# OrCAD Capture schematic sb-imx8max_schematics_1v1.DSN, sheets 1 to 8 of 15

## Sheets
1 14. HDMI_RX: size A; title: 14. HDMI_RX; rev: 1.1
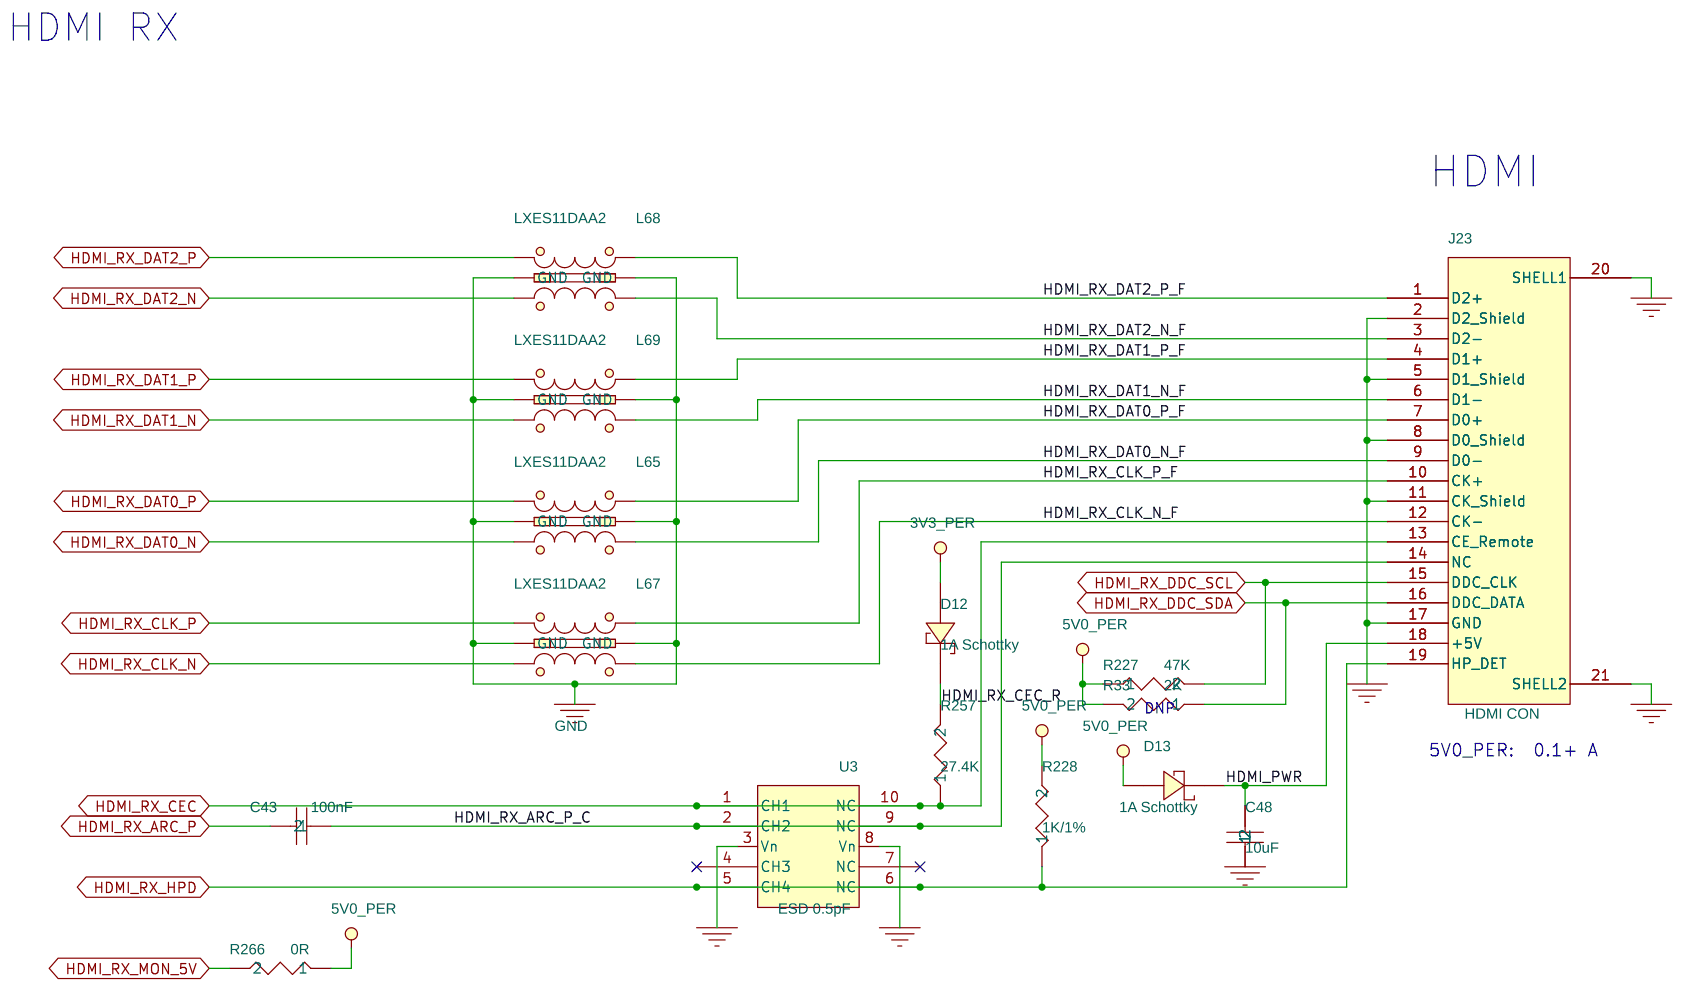
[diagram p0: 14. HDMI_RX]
2 13. AUDIO: size B; title: 13. AUDIO
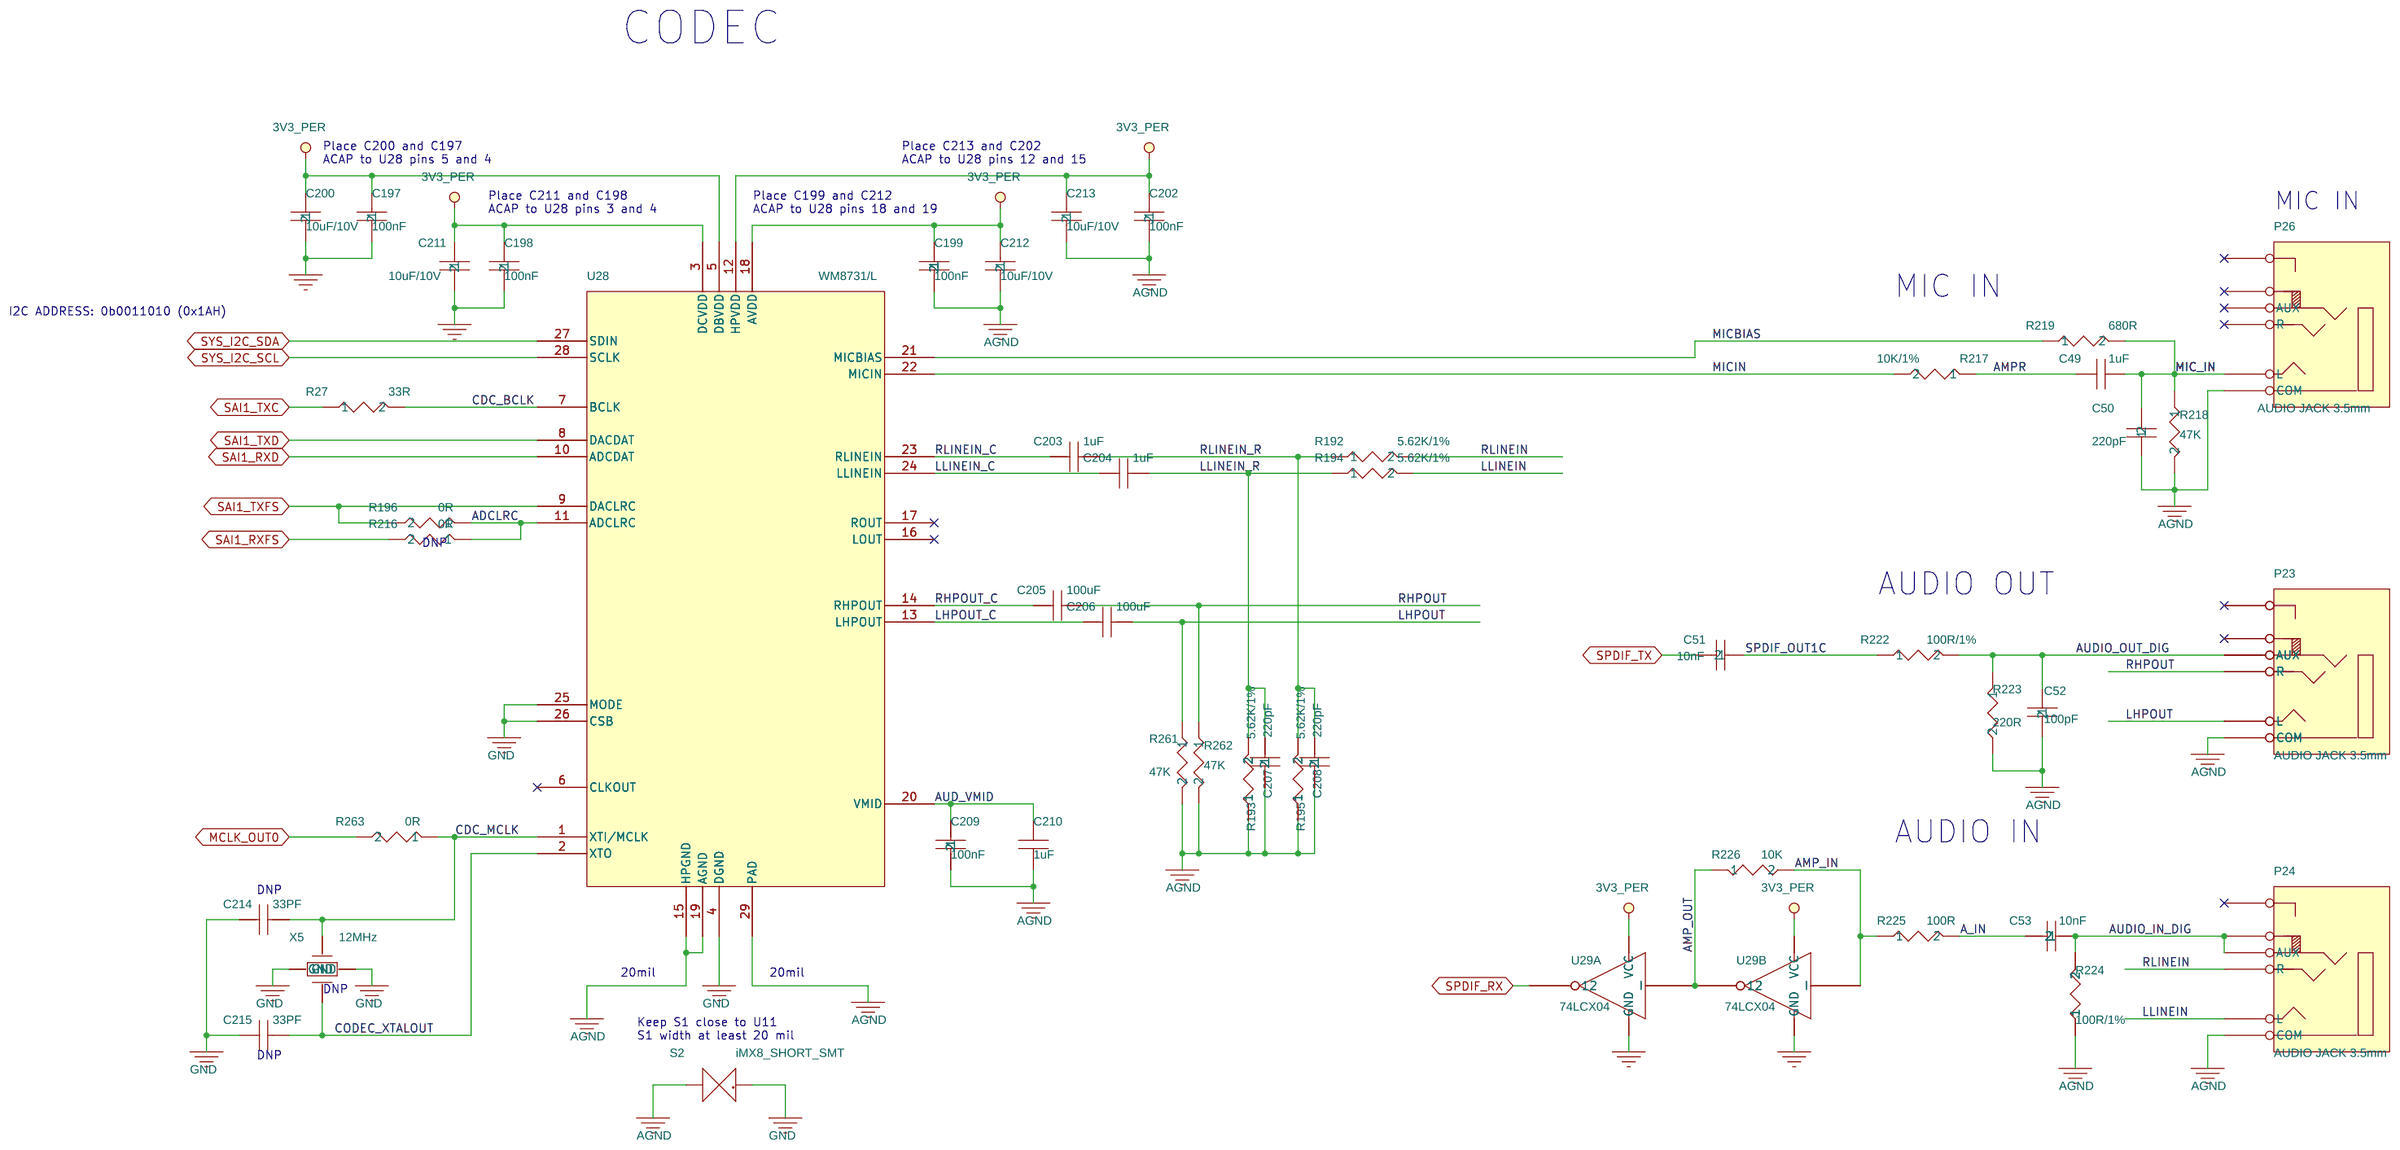
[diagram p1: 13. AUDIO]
3 12. LVDS 2CH DISPLAY: size B; title: 12. LVDS 2CH DISPLAY
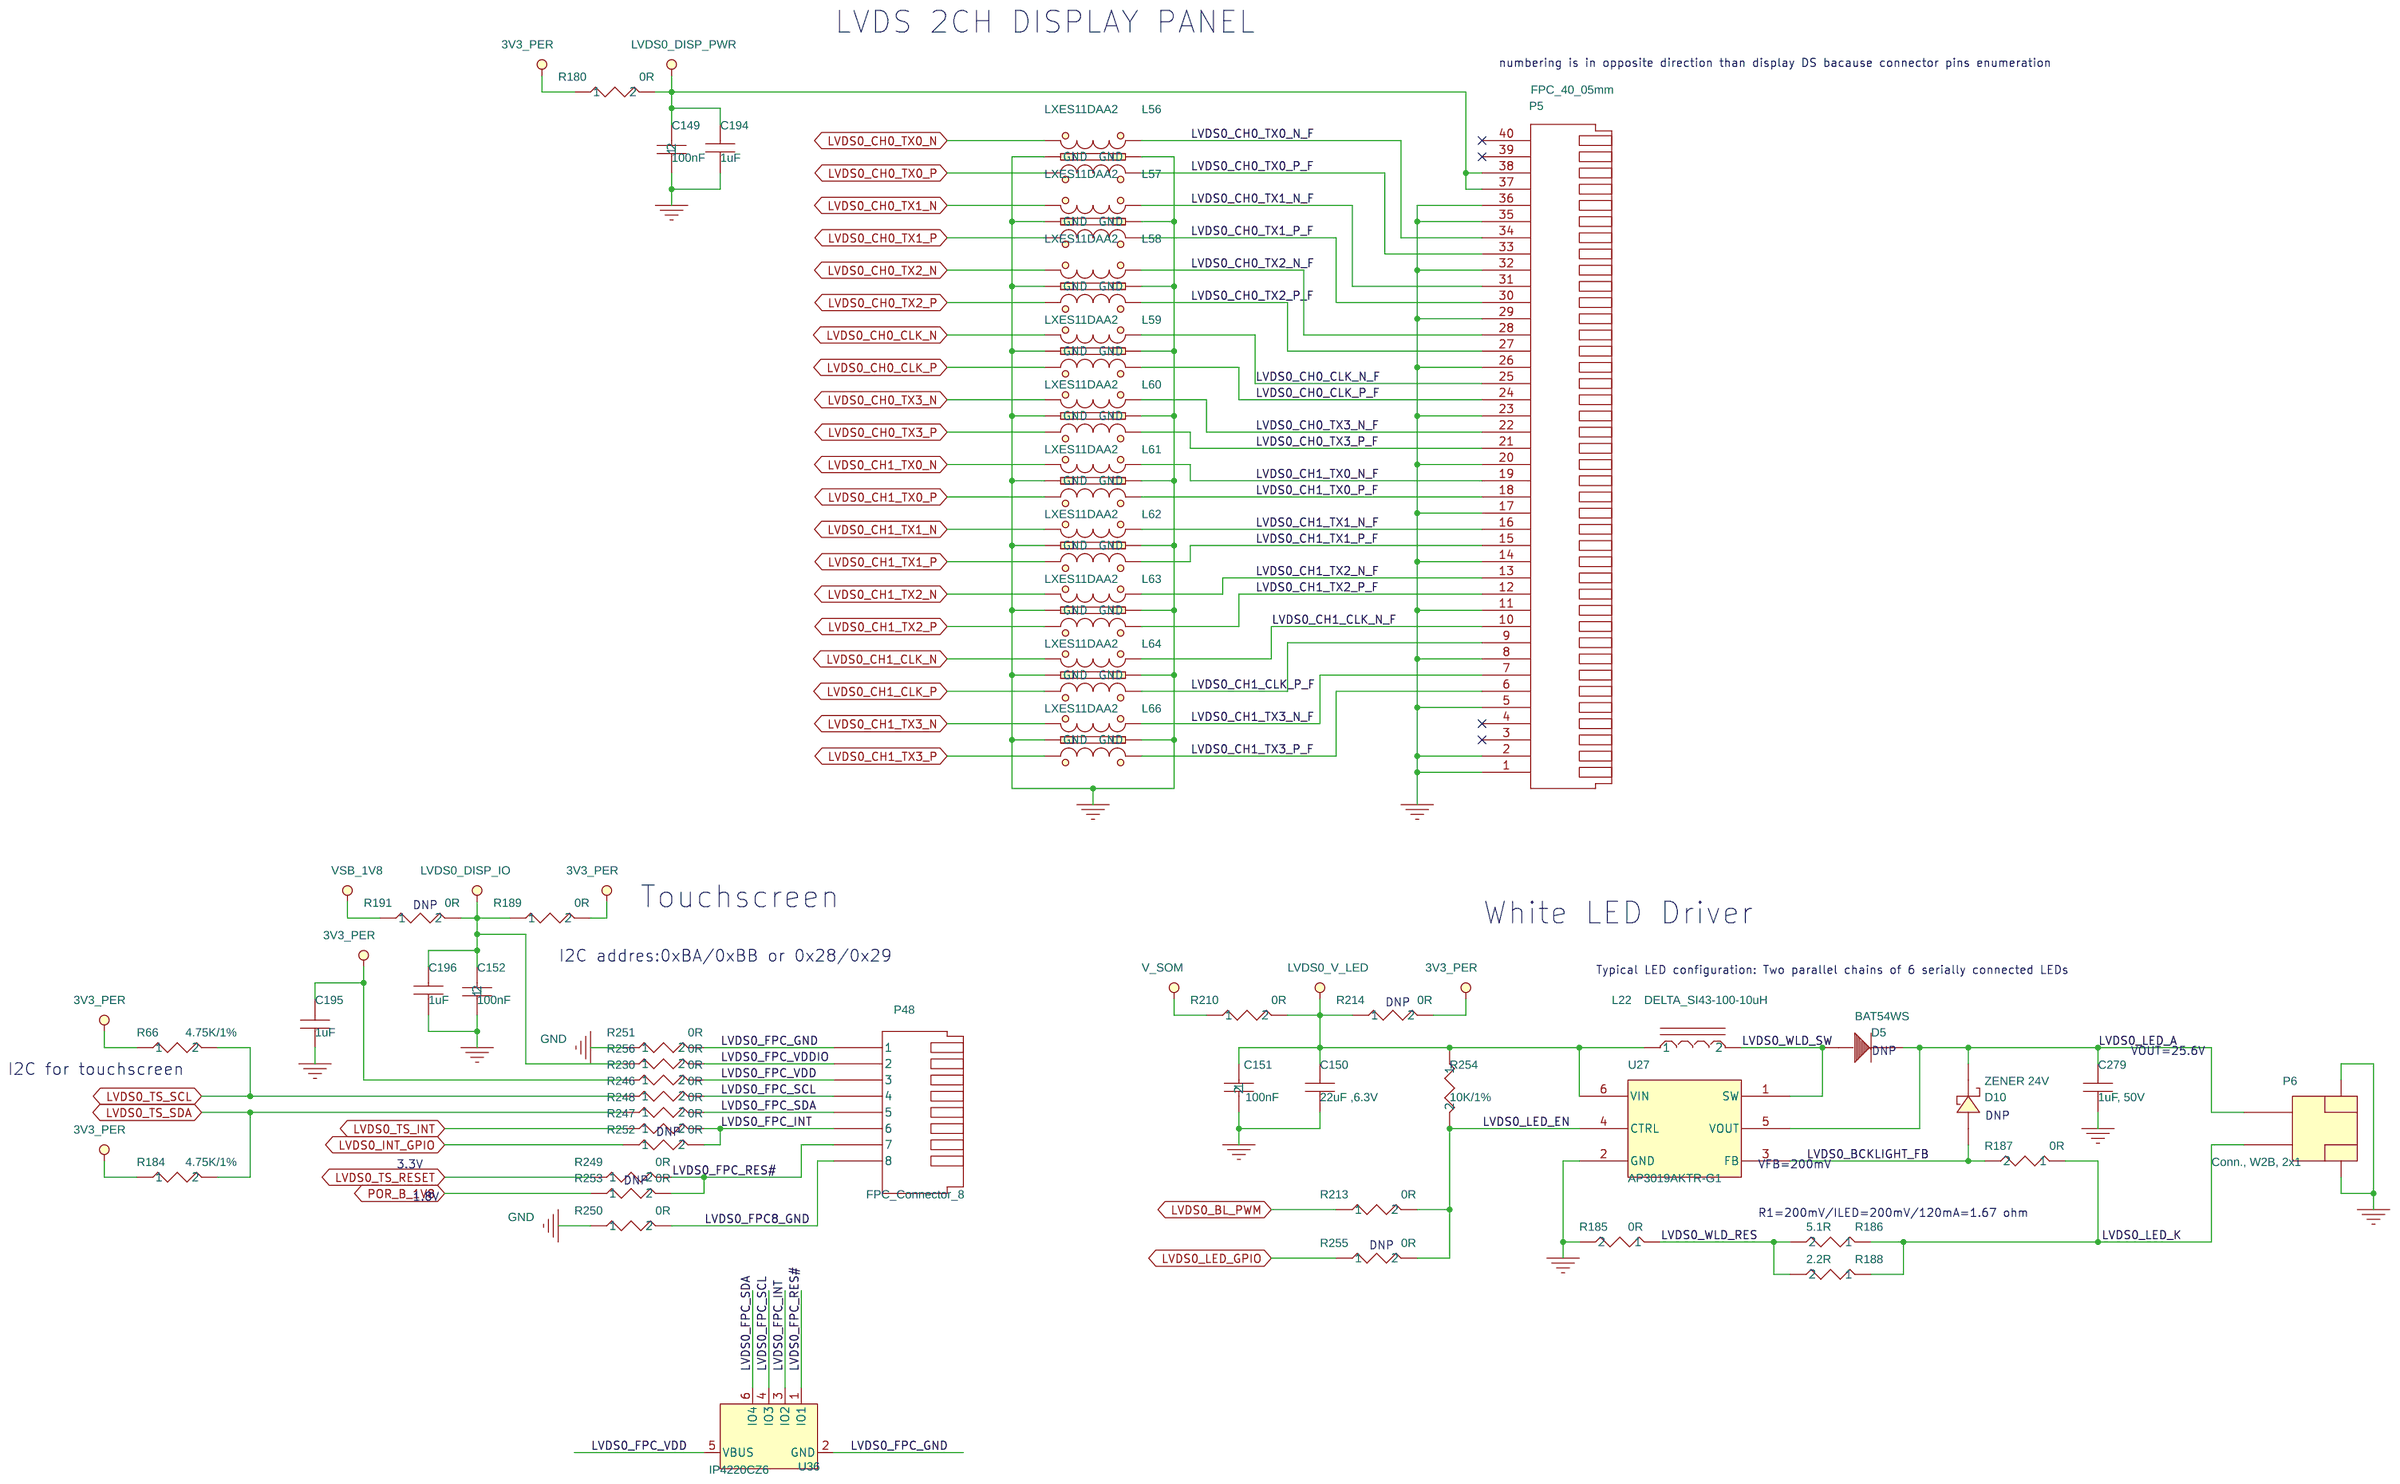
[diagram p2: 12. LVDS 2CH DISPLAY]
4 11. DISPLAYPORT DUAL MODE: size B; title: 11. DISPLAYPORT DUAL MODE
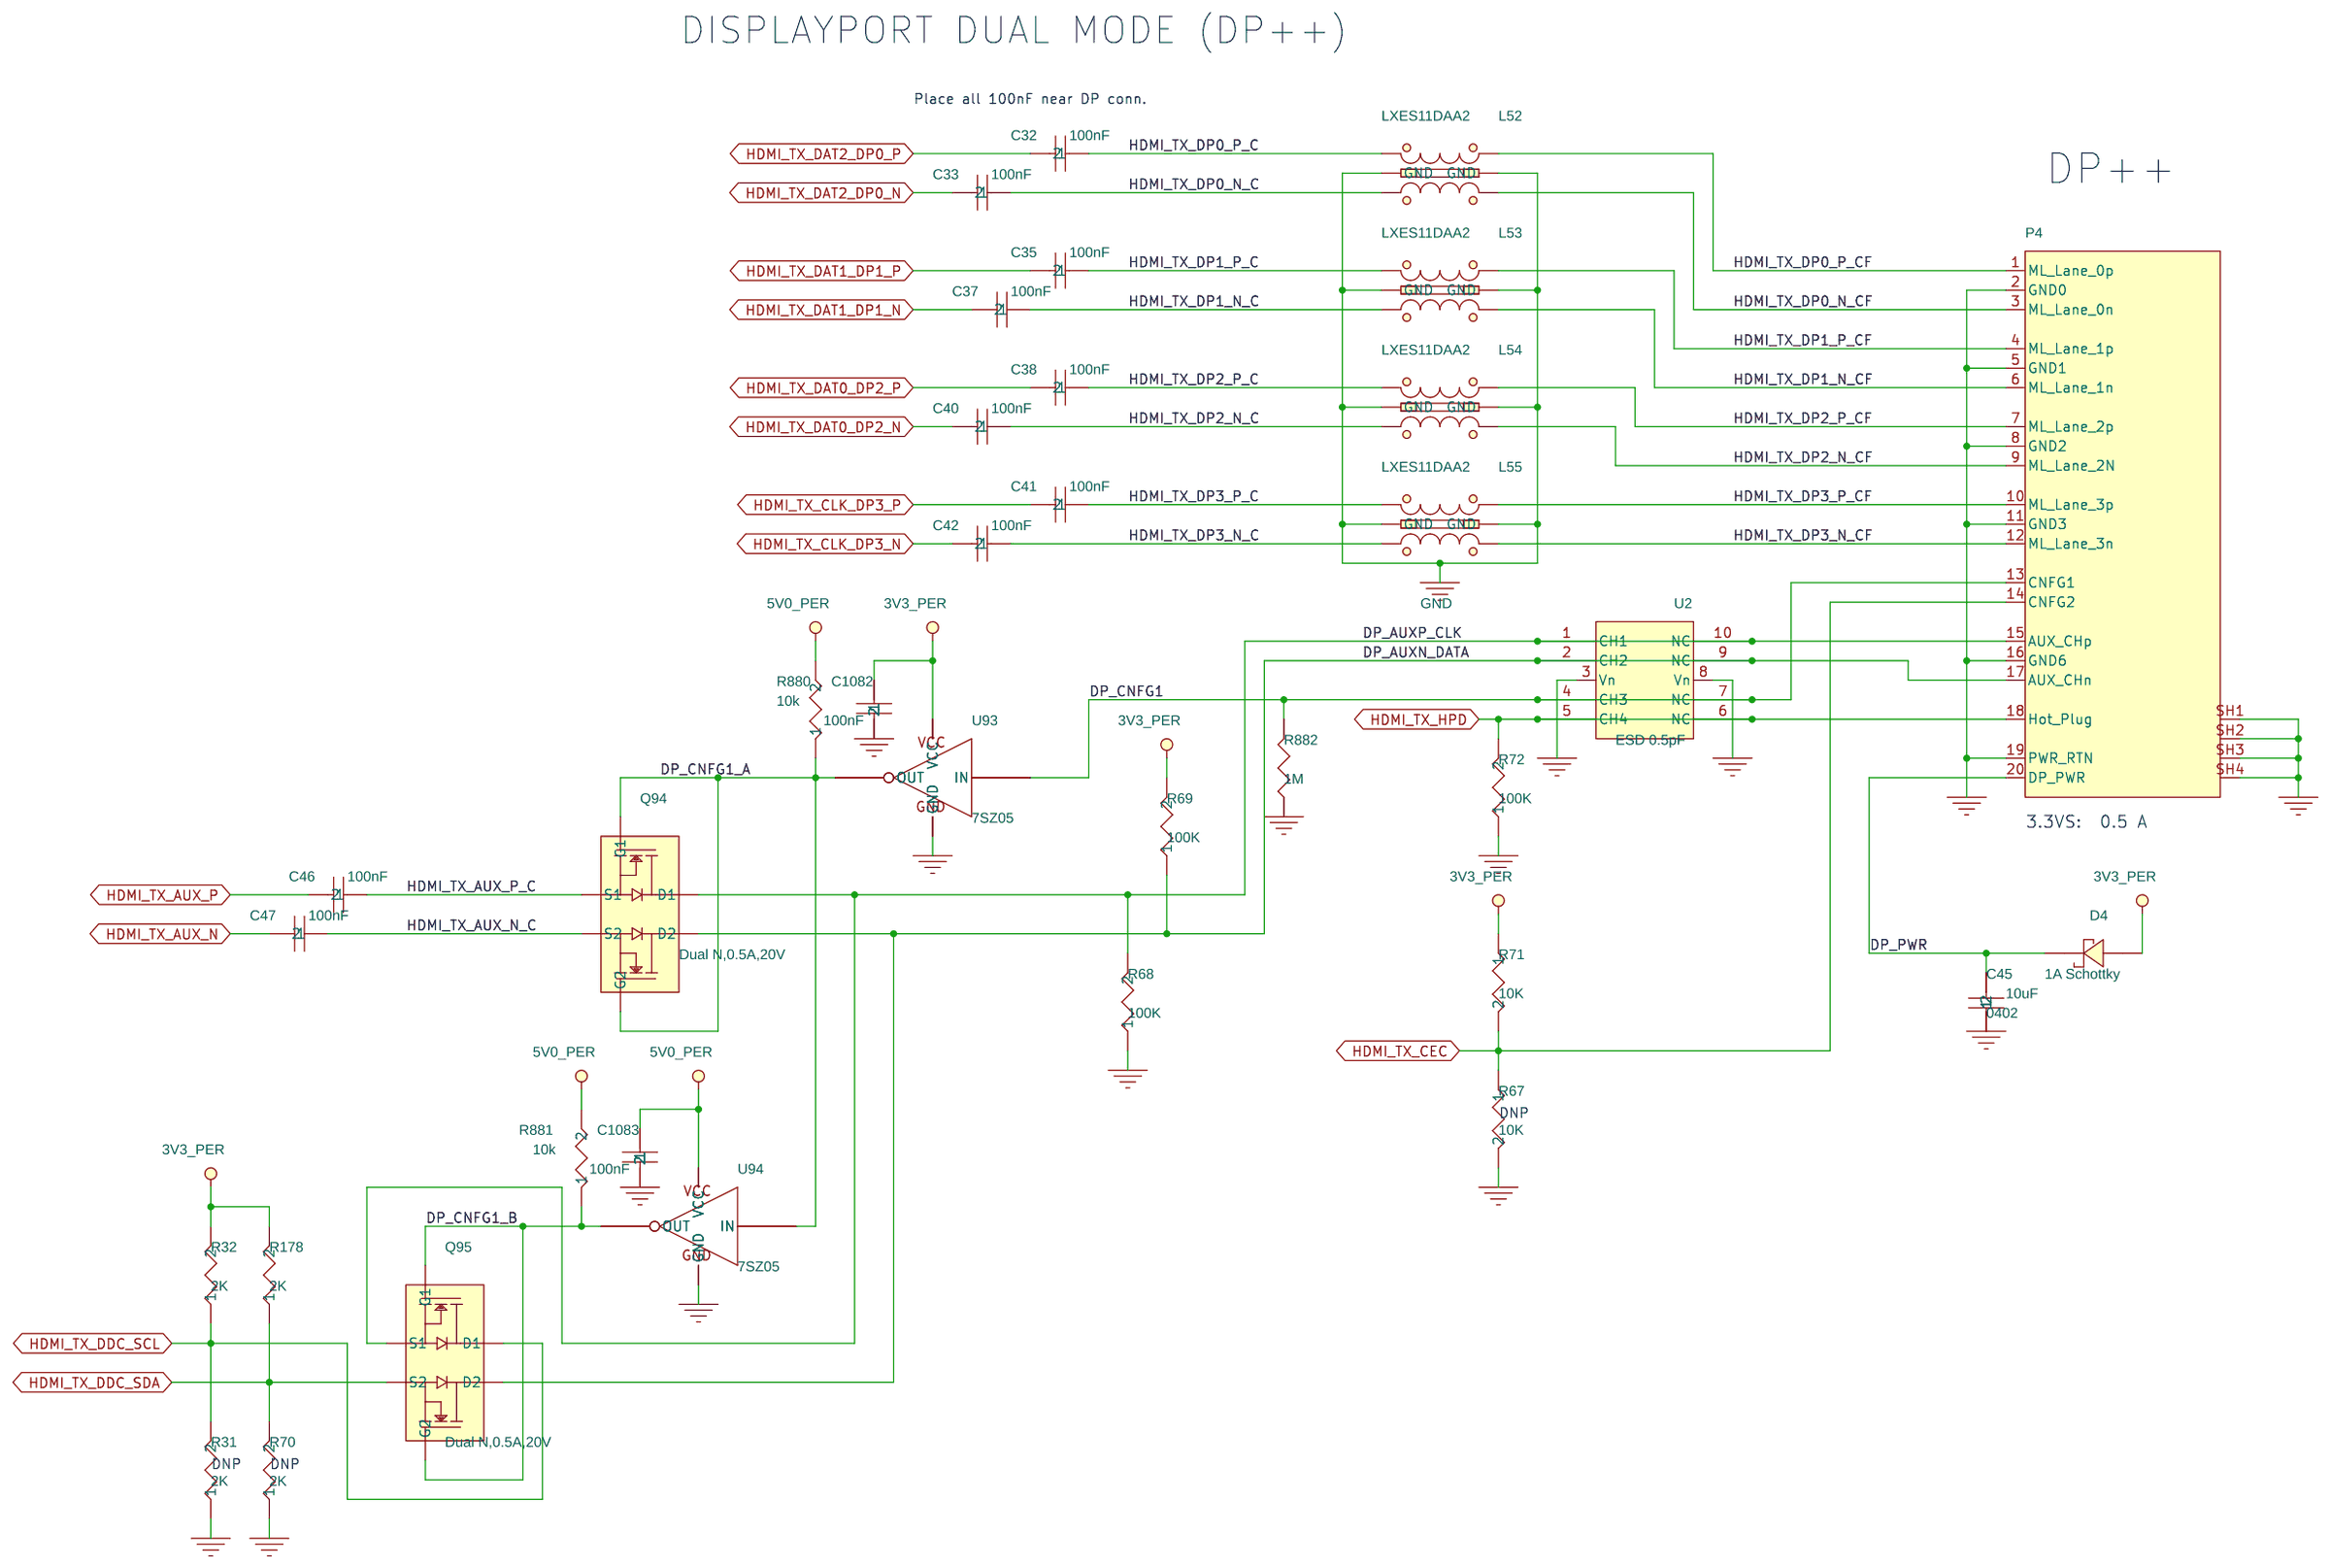
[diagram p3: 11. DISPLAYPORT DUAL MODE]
5 05. PCIe , SATA: size C; title: 05. PCIe , SATA
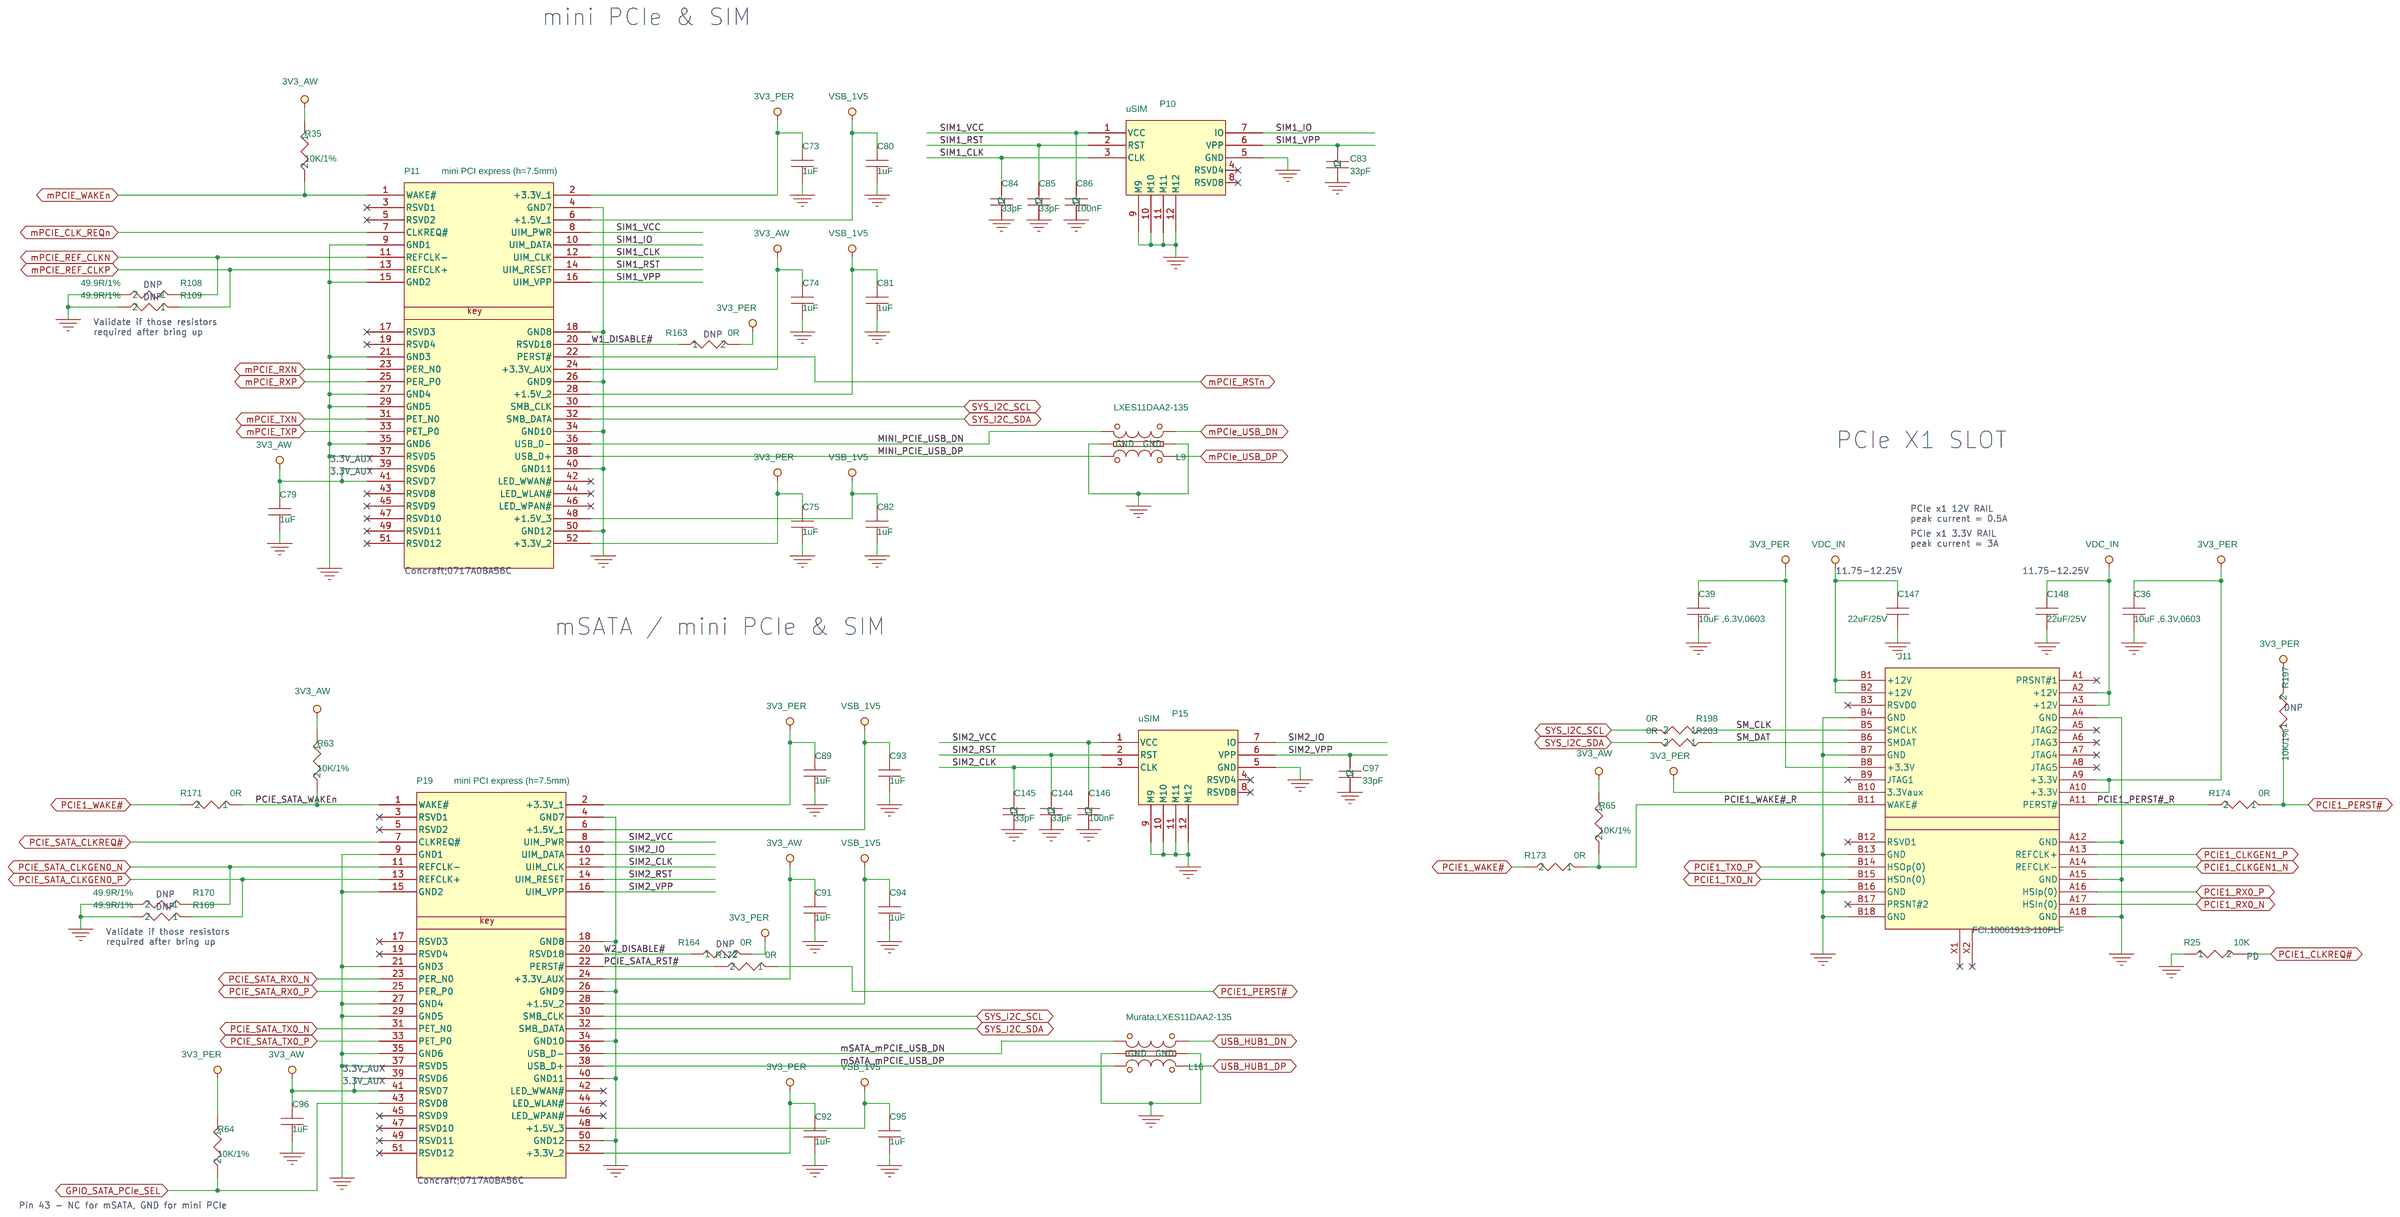
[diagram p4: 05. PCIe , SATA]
6 10. MIPI-DSI: size A3; title: 10. MIPI-DSI; note: 8010055003
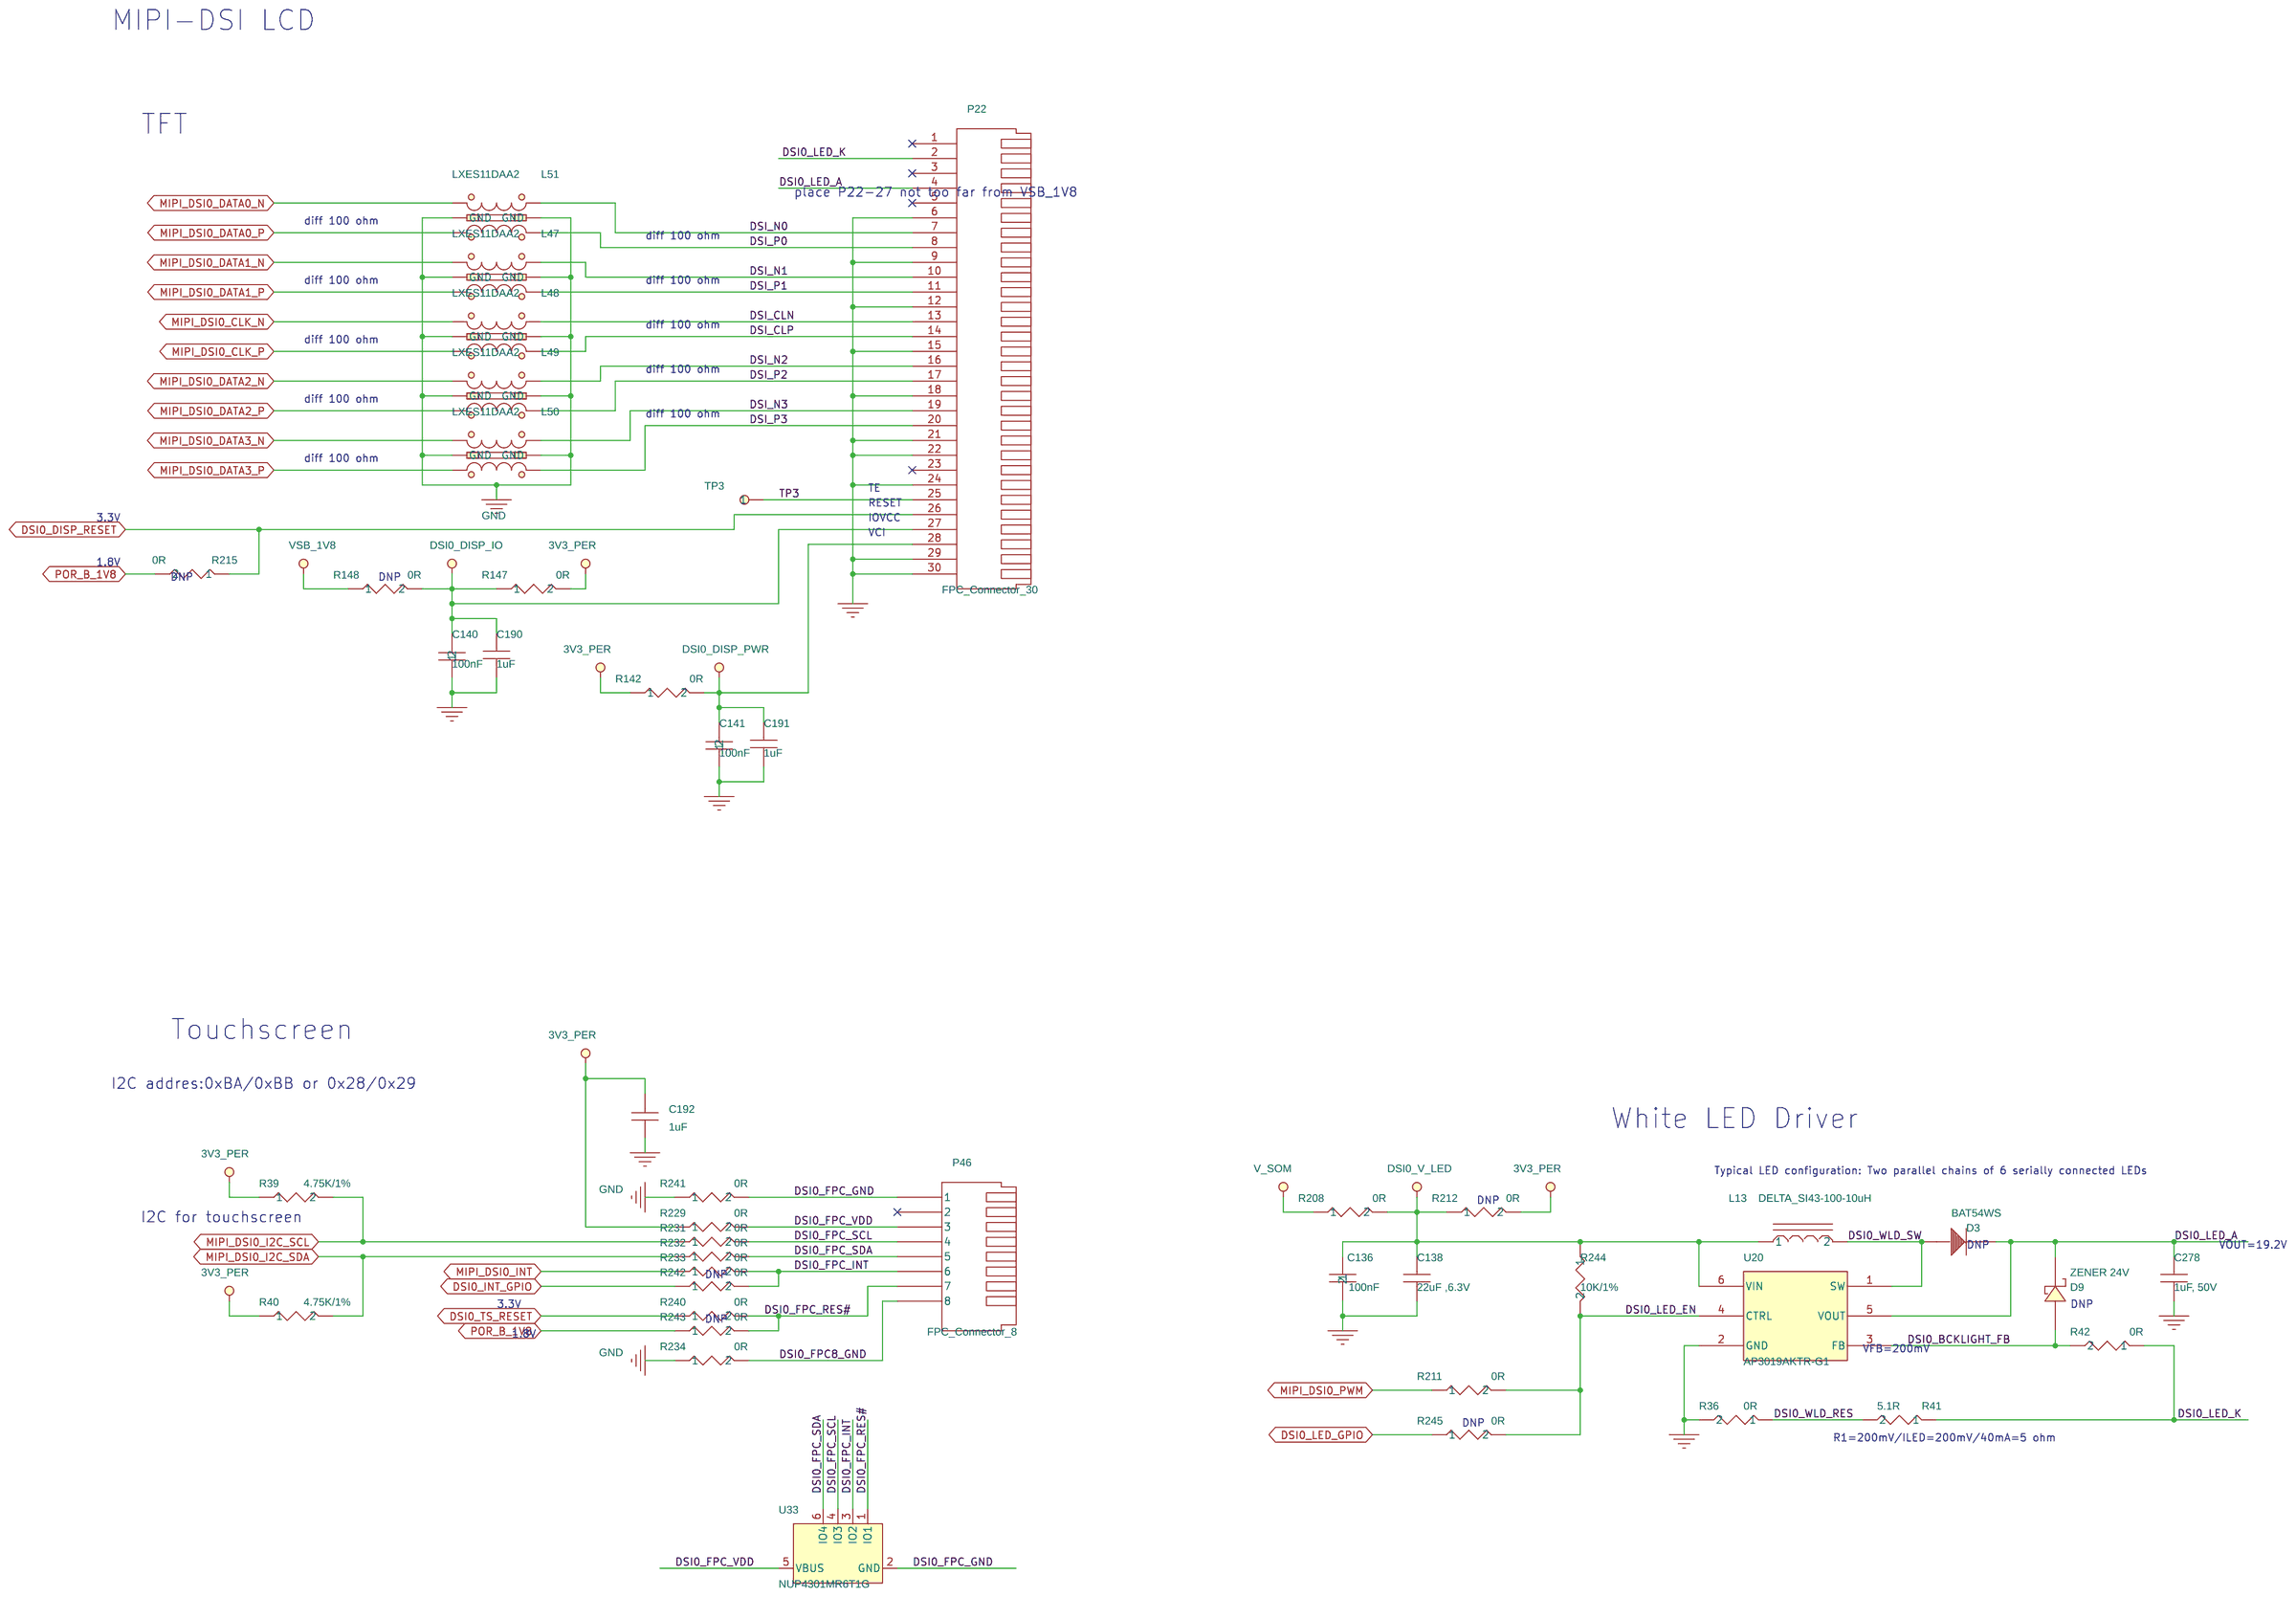
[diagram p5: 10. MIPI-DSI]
7 15. MECHANICS: size B; title: 15. MECHANICS; note: 8000064001
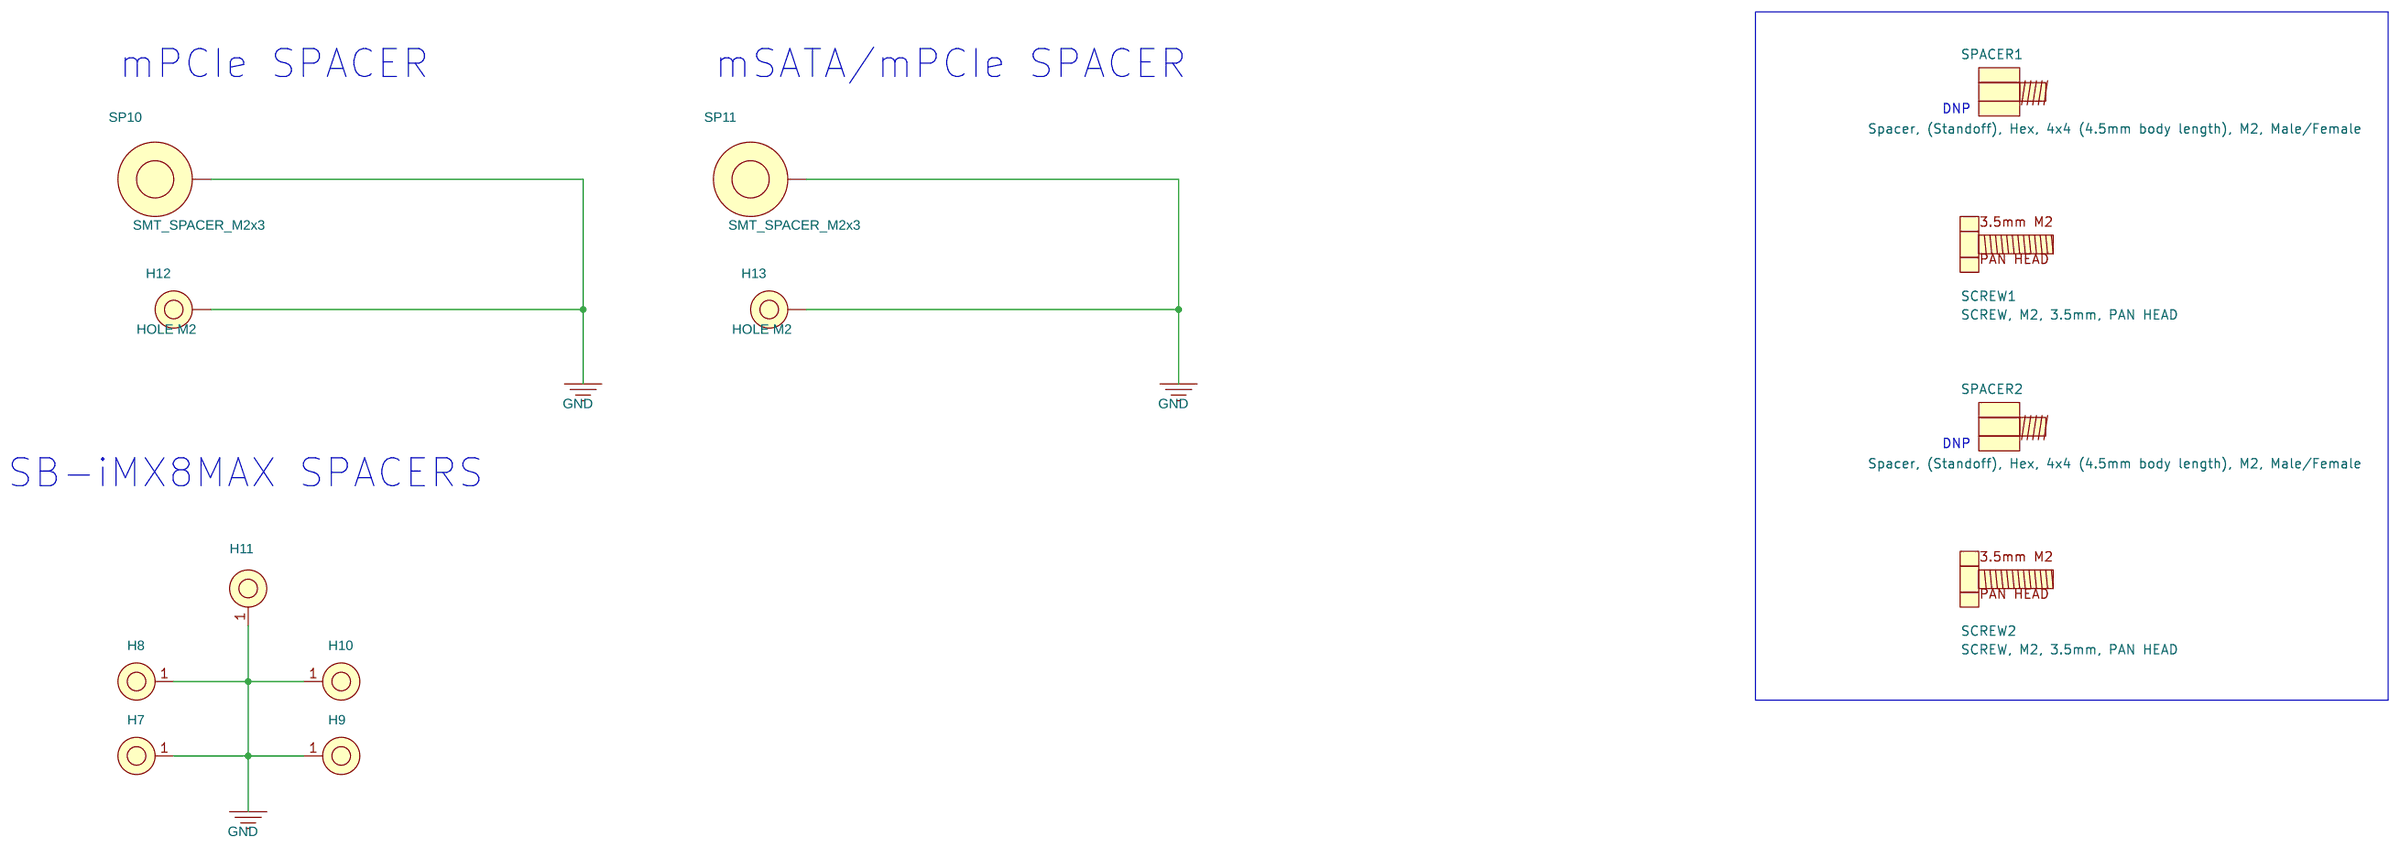
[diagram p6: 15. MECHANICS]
8 01. BLOCK & POWER DIAGRAM: size C; title: 01. BLOCK & POWER DIAGRAM; note: 8010055003
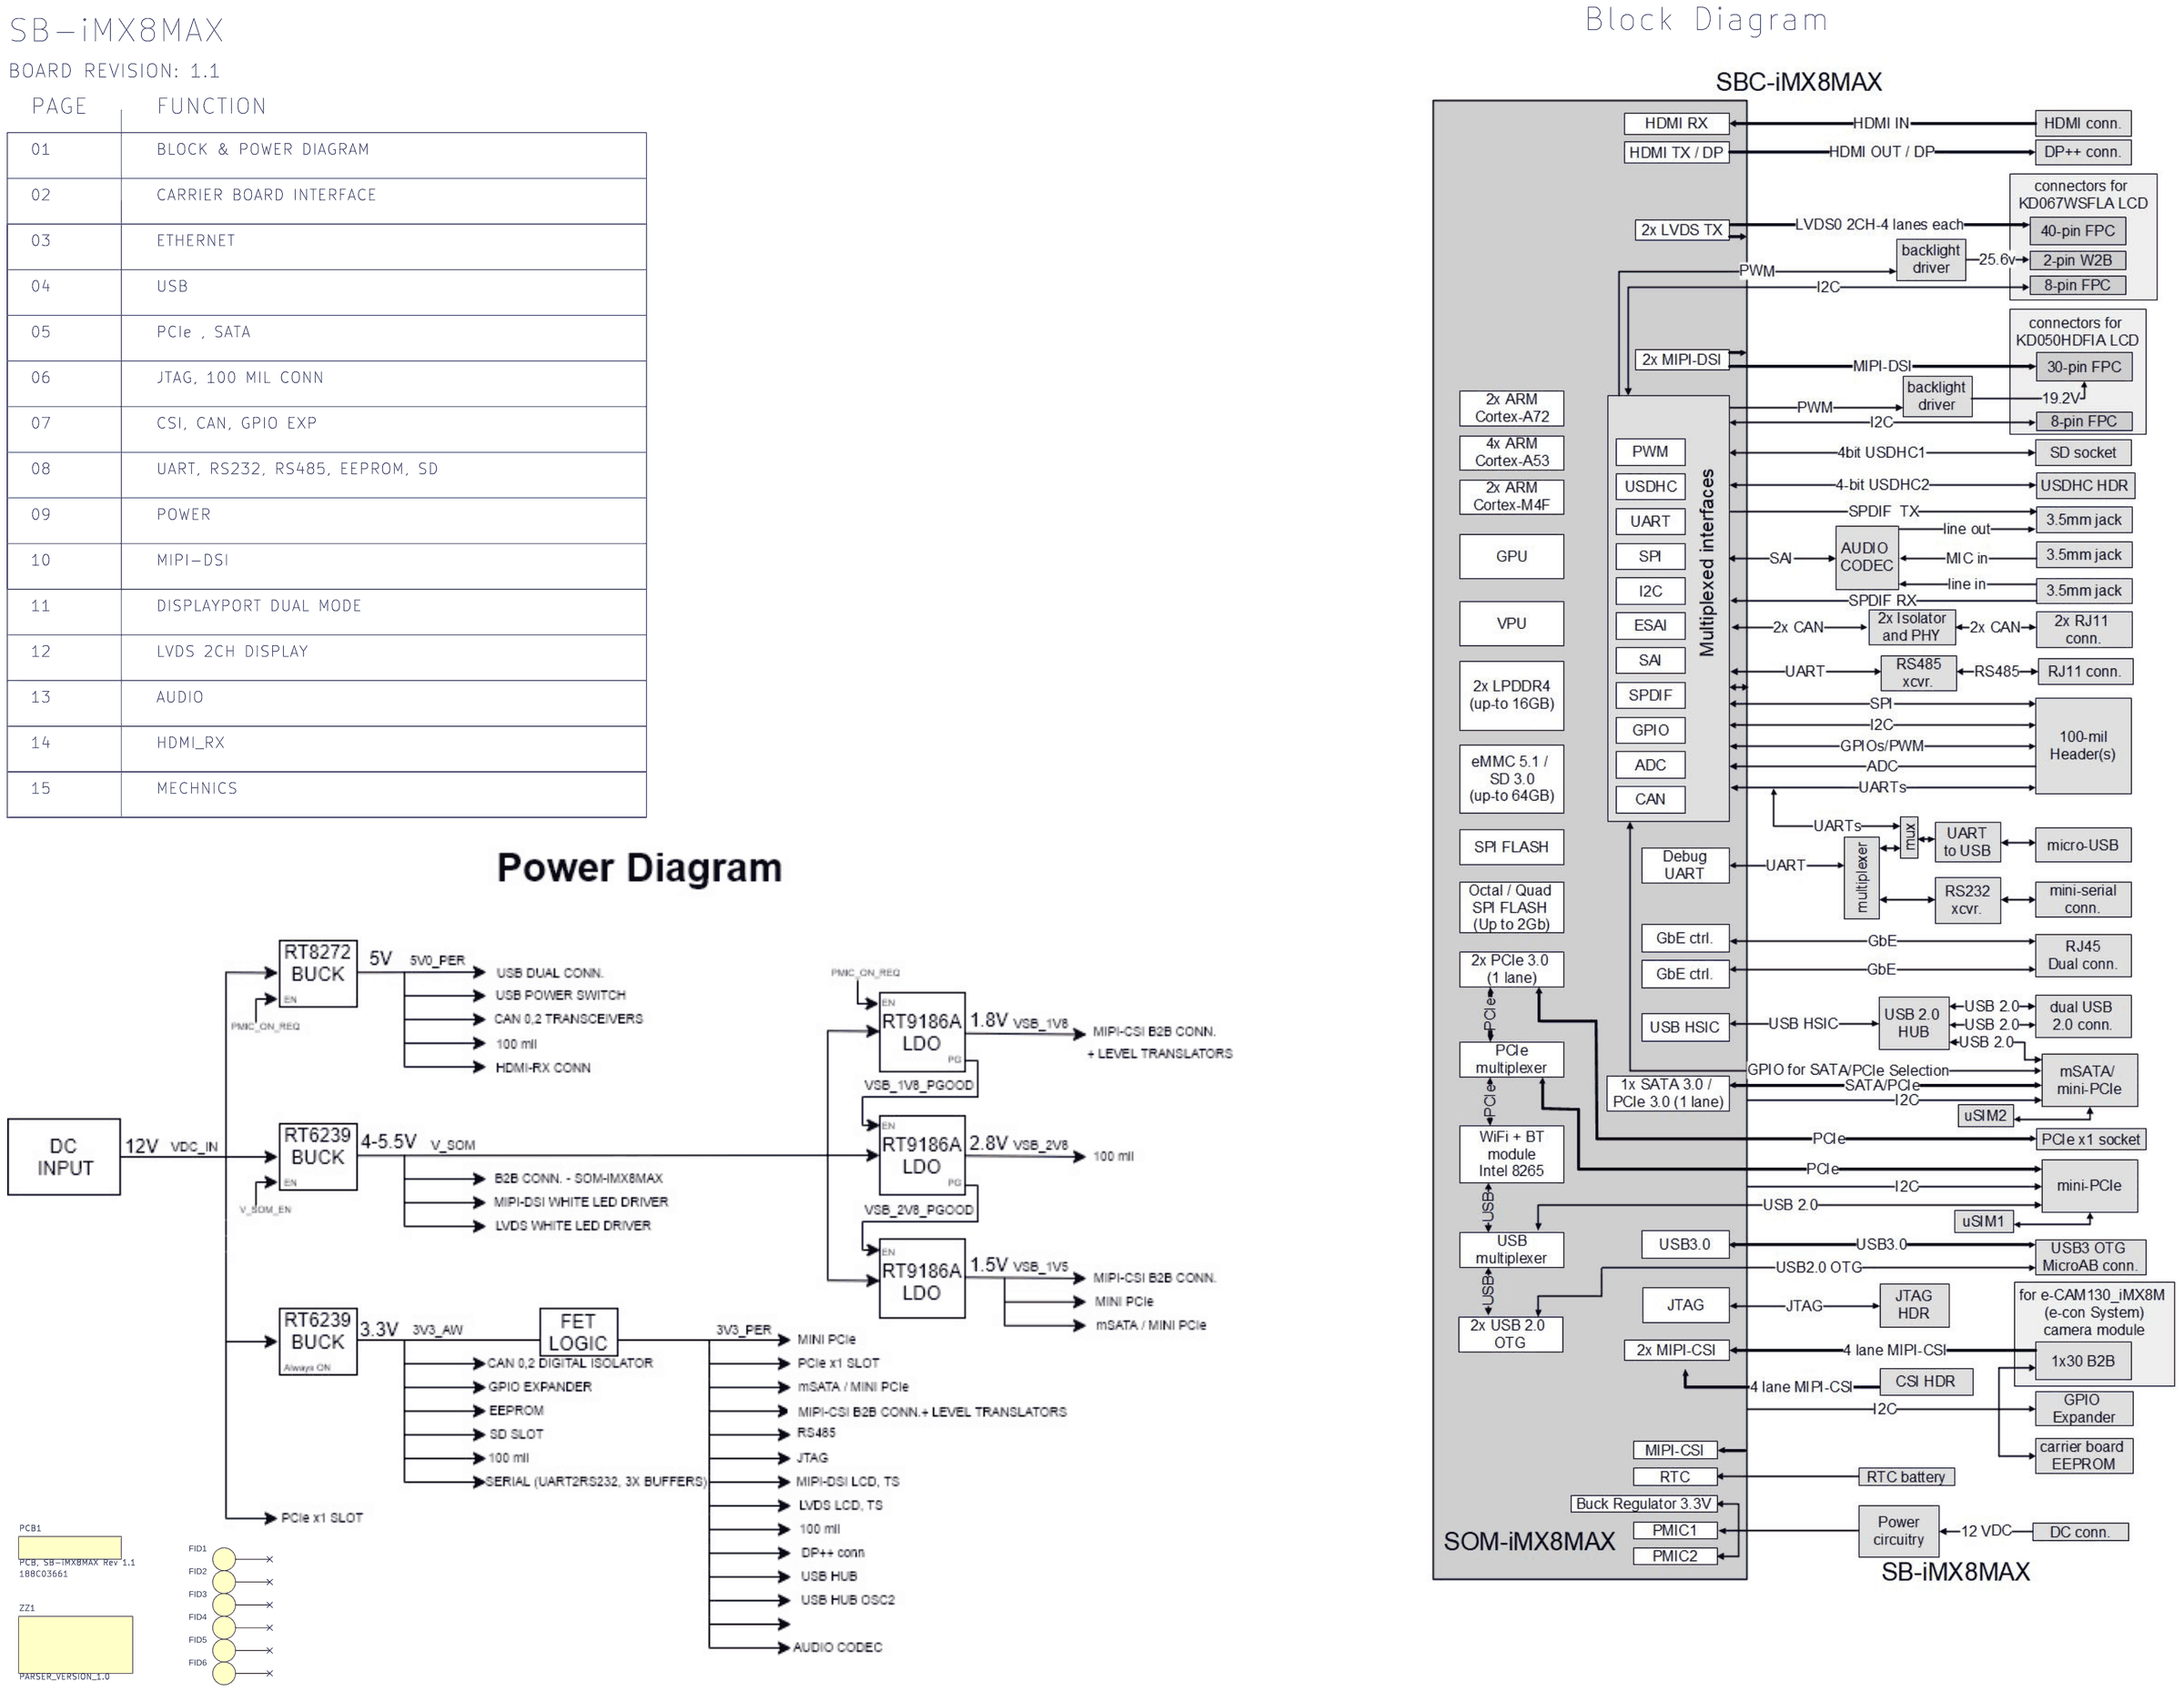
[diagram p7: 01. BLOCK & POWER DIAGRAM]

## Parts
sheet 01. BLOCK & POWER DIAGRAM
FID1  FIDUCIAL  [FIDUCIAL]
FID2  FIDUCIAL  [FIDUCIAL]
FID3  FIDUCIAL  [FIDUCIAL]
FID4  FIDUCIAL  [FIDUCIAL]
FID5  FIDUCIAL  [FIDUCIAL]
FID6  FIDUCIAL  [FIDUCIAL]
PCB1  PCB, SB-iMX8MAX Rev 1.1
ZZ1  PARSER_VERSION_1.0
sheet 05. PCIe , SATA
C36  10uF ,6.3V,0603  [RC0603]
C39  10uF ,6.3V,0603  [RC0603]
C73  1uF  [RC0402]
C74  1uF  [RC0402]
C75  1uF  [RC0402]
C79  1uF  [RC0402]
C80  1uF  [RC0402]
C81  1uF  [RC0402]
C82  1uF  [RC0402]
C83  33pF  [RC0402]
C84  33pF  [RC0402]
C85  33pF  [RC0402]
C86  100nF  [RC0402]
C89  1uF  [RC0402]
C91  1uF  [RC0402]
C92  1uF  [RC0402]
C93  1uF  [RC0402]
C94  1uF  [RC0402]
C95  1uF  [RC0402]
C96  1uF  [RC0402]
C97  33pF  [RC0402]
C144  33pF  [RC0402]
C145  33pF  [RC0402]
C146  100nF  [RC0402]
C147  22uF/25V  [C0805]
C148  22uF/25V  [C0805]
J11  FCI;10061913-110PLF  [PCIe36P1MMSM]
L9  LXES11DAA2-135  [EMI1012-ESD]
L16  Murata;LXES11DAA2-135  [EMI1012-ESD]
P10  uSIM  [SKT-MicroSIM6-SM]
P11  mini PCI express (h=7.5mm)  [MINIPCIE-4]
P15  uSIM  [SKT-MicroSIM6-SM]
P19  mini PCI express (h=7.5mm)  [MINIPCIE-4]
R25  10K  [RC0402]
R35  10K/1%  [RC0402]
R63  10K/1%  [RC0402]
R64  10K/1%  [RC0402]
R65  10K/1%  [RC0402]
R108  49.9R/1%  [RC0402]
R109  49.9R/1%  [RC0402]
R163  0R  [RC0402]
R164  0R  [RC0402]
R169  49.9R/1%  [RC0402]
R170  49.9R/1%  [RC0402]
R171  0R  [RC0402]
R172  0R  [RC0402]
R173  0R  [RC0402]
R174  0R  [RC0402]
R197  10K/1%  [RC0402]
R198  0R  [RC0402]
R203  0R  [RC0402]
sheet 10. MIPI-DSI
C136  100nF  [RC0402]
C138  22uF ,6.3V  [RC0603]
C140  100nF  [RC0402]
C141  100nF  [RC0402]
C190  1uF  [RC0402]
C191  1uF  [RC0402]
C192  1uF  [RC0402]
C278  1uF, 50V  [RC0603]
D3  BAT54WS  [SOD-323]
D9  ZENER 24V  [SOD-123]
L13  DELTA_SI43-100-10uH  [IND4x4x2_5]
L47  LXES11DAA2  [EMI1012-ESD]
L48  LXES11DAA2  [EMI1012-ESD]
L49  LXES11DAA2  [EMI1012-ESD]
L50  LXES11DAA2  [EMI1012-ESD]
L51  LXES11DAA2  [EMI1012-ESD]
P22  FPC_Connector_30  [FPC_30]
P46  FPC_Connector_8  [FPC_8]
R36  0R  [RC0402]
R39  4.75K/1%  [RC0402]
R40  4.75K/1%  [RC0402]
R41  5.1R  [RC0402]
R42  0R  [RC0402]
R142  0R  [RC0402]
R147  0R  [RC0402]
R148  0R  [RC0402]
R208  0R  [RC0402]
R211  0R  [RC0402]
R212  0R  [RC0402]
R215  0R  [RC0402]
R229  0R  [RC0402]
R231  0R  [RC0402]
R232  0R  [RC0402]
R233  0R  [RC0402]
R234  0R  [RC0402]
R240  0R  [RC0402]
R241  0R  [RC0402]
R242  0R  [RC0402]
R243  0R  [RC0402]
R244  10K/1%  [RC0402]
R245  0R  [RC0402]
TP3  TESTPOINT  [TESTPOINT]
U20  AP3019AKTR-G1
U33  NUP4301MR6T1G  [SOT23-6L]
sheet 11. DISPLAYPORT DUAL MODE
C32  100nF  [RC0402]
C33  100nF  [RC0402]
C35  100nF  [RC0402]
C37  100nF  [RC0402]
C38  100nF  [RC0402]
C40  100nF  [RC0402]
C41  100nF  [RC0402]
C42  100nF  [RC0402]
C45  10uF  [0402]
C46  100nF  [RC0402]
C47  100nF  [RC0402]
C1082  100nF  [RC0402]
C1083  100nF  [RC0402]
D4  1A Schottky  [SOD-123]
L52  LXES11DAA2  [EMI1012-ESD]
L53  LXES11DAA2  [EMI1012-ESD]
L54  LXES11DAA2  [EMI1012-ESD]
L55  LXES11DAA2  [EMI1012-ESD]
P4  CON_DISPLAYPORT RA  [DP-F-RA-SM]
Q94  Dual N,0.5A,20V  [SOT-563-6]
Q95  Dual N,0.5A,20V  [SOT-563-6]
R31  2K  [RC0402]
R32  2K  [RC0402]
R67  10K  [RC0402]
R68  100K  [RC0402]
R69  100K  [RC0402]
R70  2K  [RC0402]
R71  10K  [RC0402]
R72  100K  [RC0402]
R178  2K  [RC0402]
R880  10k  [RC0402]
R881  10k  [RC0402]
R882  1M  [RC0402]
U2  ESD 0.5pF  [DFN-X2510D-10]
U93  7SZ05  [SC70]
U94  7SZ05  [SC70]
sheet 12. LVDS 2CH DISPLAY
C149  100nF  [RC0402]
C150  22uF ,6.3V  [RC0603]
C151  100nF  [RC0402]
C152  100nF  [RC0402]
C194  1uF  [RC0402]
C195  1uF  [RC0402]
C196  1uF  [RC0402]
C279  1uF, 50V  [RC0603]
D5  BAT54WS  [SOD-323]
D10  ZENER 24V  [SOD-123]
L22  DELTA_SI43-100-10uH  [IND4x4x2_5]
L56  LXES11DAA2  [EMI1012-ESD]
L57  LXES11DAA2  [EMI1012-ESD]
L58  LXES11DAA2  [EMI1012-ESD]
L59  LXES11DAA2  [EMI1012-ESD]
L60  LXES11DAA2  [EMI1012-ESD]
L61  LXES11DAA2  [EMI1012-ESD]
L62  LXES11DAA2  [EMI1012-ESD]
L63  LXES11DAA2  [EMI1012-ESD]
L64  LXES11DAA2  [EMI1012-ESD]
L66  LXES11DAA2  [EMI1012-ESD]
P5  FPC_40_05mm  [FPC05SM40-1]
P6  Conn., W2B, 2x1  [1x2W2B1_25RASM]
P48  FPC_Connector_8  [FPC_8]
R66  4.75K/1%  [RC0402]
R180  0R  [RC0402]
R184  4.75K/1%  [RC0402]
R185  0R  [RC0402]
R186  5.1R  [RC0402]
R187  0R  [RC0402]
R188  2.2R  [RC0402]
R189  0R  [RC0402]
R191  0R  [RC0402]
R210  0R  [RC0402]
R213  0R  [RC0402]
R214  0R  [RC0402]
R230  0R  [RC0402]
R246  0R  [RC0402]
R247  0R  [RC0402]
R248  0R  [RC0402]
R249  0R  [RC0402]
R250  0R  [RC0402]
R251  0R  [RC0402]
R252  0R  [RC0402]
R253  0R  [RC0402]
R254  10K/1%  [RC0402]
R255  0R  [RC0402]
R256  0R  [RC0402]
U27  AP3019AKTR-G1
U36  IP4220CZ6  [SOT23-6L]
sheet 13. AUDIO
C49  1uF  [RC0402]
C50  220pF  [RC0603]
C51  10nF  [RC0402]
C52  100pF  [RC0402]
C53  10nF  [RC0402]
C197  100nF  [RC0402]
C198  100nF  [RC0402]
C199  100nF  [RC0402]
C200  10uF/10V  [0402]
C202  100nF  [RC0402]
C203  1uF  [RC0402]
C204  1uF  [RC0402]
C205  100uF  [C1206]
C206  100uF  [C1206]
C207  220pF  [RC0603]
C208  220pF  [RC0603]
C209  100nF  [RC0402]
C210  1uF  [RC0402]
C211  10uF/10V  [0402]
C212  10uF/10V  [0402]
C213  10uF/10V  [0402]
C214  33PF  [RC0402]
C215  33PF  [RC0402]
P23  AUDIO JACK 3.5mm  [AJ35-4P-SW-SM]
P24  AUDIO JACK 3.5mm  [AJ35-4P-SW-SM]
P26  AUDIO JACK 3.5mm  [AJ35-4P-SW-SM]
R27  33R  [RC0402]
R192  5.62K/1%  [RC0402]
R193  5.62K/1%  [RC0402]
R194  5.62K/1%  [RC0402]
R195  5.62K/1%  [RC0402]
R196  0R  [RC0402]
R216  0R  [RC0402]
R217  10K/1%  [RC0402]
R218  47K  [RC0402]
R219  680R  [RC0402]
R222  100R/1%  [RC0402]
R223  220R  [RC0402]
R224  100R/1%  [RC0402]
R225  100R  [RC0402]
R226  10K  [RC0402]
R261  47K  [RC0402]
R262  47K  [RC0402]
R263  0R  [RC0402]
S2  iMX8_SHORT_SMT  [iMX8_SHORT_SMT]
U28  WM8731/L  [MO-220VHHD-1]
U29  74LCX04  [TSSOP-14]  (sections A,B)
X5  12MHz  [OSC3225]
sheet 14. HDMI_RX
C43  100nF  [RC0402]
C48  10uF  [0402]
D12  1A Schottky  [SOD-123]
D13  1A Schottky  [SOD-123]
J23  HDMI CON  [HDMI-A19-RASM]
L65  LXES11DAA2  [EMI1012-ESD]
L67  LXES11DAA2  [EMI1012-ESD]
L68  LXES11DAA2  [EMI1012-ESD]
L69  LXES11DAA2  [EMI1012-ESD]
R33  2K  [RC0402]
R227  47K  [RC0402]
R228  1K/1%  [RC0402]
R257  27.4K  [RC0402]
R266  0R  [RC0402]
U3  ESD 0.5pF  [DFN-X2510D-10]
sheet 15. MECHANICS
H7  MechHole  [M3PAD]
H8  MechHole  [M3PAD]
H9  MechHole  [M3PAD]
H10  MechHole  [M3PAD]
H11  MechHole  [M3PAD]
H12  HOLE M2  [M2PAD]
H13  HOLE M2  [M2PAD]
SCREW1  SCREW, M2, 3.5mm, PAN HEAD  [NONE]
SCREW2  SCREW, M2, 3.5mm, PAN HEAD  [NONE]
SP10  SMT_SPACER_M2x3  [MINIPCIE-4-Spacer]
SP11  SMT_SPACER_M2x3  [MINIPCIE-4-Spacer]
SPACER1  Spacer, (Standoff), Hex, 4x4 (4.5mm body length), M2, Male/Female  [NONE]
SPACER2  Spacer, (Standoff), Hex, 4x4 (4.5mm body length), M2, Male/Female  [NONE]

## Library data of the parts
FID1-FID6 = TESTPOINT_2: CLABCONF0: DNP
PCB1 = PCB,_EM-X270_Rev_1_0.1: CLABCONF0: SB-iMX8MAX; P/N: 188C03661
ZZ1 = PARSER_VERSION_1_1.0: CLABCONF0: DNP
C36 = Cap.,10uF,6.3V,0603,X5R: CLABCONF0: SB-iMX8MAX
C39 = Cap.,10uF,6.3V,0603,X5R_1: CLABCONF0: SB-iMX8MAX
C49 C73-C75 C79-C82 C89 C91-C96 C190-C192 C194-C196 C203 C204 C210 = 1uF,X5R,6.3V,0402: CLABCONF0: SB-iMX8MAX
C83 = 15pF,_50V,_NPO,_5%,_0402: CLABCONF0: SB-iMX8MAX; P/N: 151K33000S
C84 = 15pF,_50V,_NPO,_5%,_0402_4: CLABCONF0: SB-iMX8MAX; P/N: 151K33000S
C85 = 15pF,_50V,_NPO,_5%,_0402_3: CLABCONF0: SB-iMX8MAX; P/N: 151K33000S
C41 C86 = 15pF,_50V,_NPO,_5%,_0402_5: CLABCONF0: SB-iMX8MAX; P/N: 151B10400S
C97 = 15pF,_50V,_NPO,_5%,_0402_7: CLABCONF0: SB-iMX8MAX; P/N: 151K33000S
C144 = 15pF,_50V,_NPO,_5%,_0402_6: CLABCONF0: SB-iMX8MAX; P/N: 151K33000S
C145 = 15pF,_50V,_NPO,_5%,_0402_1: CLABCONF0: SB-iMX8MAX; P/N: 151K33000S
C38 C146 = 15pF,_50V,_NPO,_5%,_0402_2: CLABCONF0: SB-iMX8MAX; P/N: 151B10400S
C147 = 22uF,25V,_0805: CLABCONF0: SB-iMX8MAX
C148 = 22uF,25V,_0805_1: CLABCONF0: SB-iMX8MAX
J11 = Conn.,_PCIEx1,_SMT: CLABCONF0: SB-iMX8MAX; P/N: 182K03601S
L9 L16 L47-L69 = ESD_CHOKE_DIFFx2_10: CLABCONF0: SB-iMX8MAX; P/N: 142D11801S
P10 P15 = uSIM_SOCKET_0: CLABCONF0: SB-iMX8MAX
P11 P19 = mini_PCIe_0: CLABCONF0: SB-iMX8MAX; P/N: 182K05201S
R25 = 1M_,5%,_0402: CLABCONF0: SB-iMX8MAX; P/N: 161C10021S
R35 = 10K,1%,0402,1_16W_3: CLABCONF0: SB-iMX8MAX
R63 R217 = 10K,1%,0402,1_16W_1: CLABCONF0: SB-iMX8MAX
R64 = 10K,1%,0402,1_16W_4: CLABCONF0: SB-iMX8MAX
R65 = 10K,1%,0402,1_16W_2: CLABCONF0: SB-iMX8MAX
R108 = 49.9R_1%,_0402_2: CLABCONF0: DNP
R109 = 49.9R_1%,_0402_1: CLABCONF0: DNP
R163 = 0R,_0402_1_3: CLABCONF0: DNP
R164 = 0R,_0402_1_2: CLABCONF0: DNP
R169 = 49.9R_1%,_0402_3: CLABCONF0: DNP
R170 = 49.9R_1%,_0402: CLABCONF0: DNP
R147 R171 R189 = 0R,_0402_1: CLABCONF0: SB-iMX8MAX
R172 = 0R,_0402_1_1: CLABCONF0: SB-iMX8MAX
R173 = 0R,_0402_1_7: CLABCONF0: SB-iMX8MAX
R174 = 0R,_0402_1_5: CLABCONF0: SB-iMX8MAX
R197 = 10K,1%,0402,1_16W: CLABCONF0: DNP
R198 = 0R,_0402_1_4: CLABCONF0: SB-iMX8MAX
R203 = 0R,_0402_1_6: CLABCONF0: SB-iMX8MAX
C136 C149 C197 = 100nF,_10V,_X7R,_10%,_0402: CLABCONF0: SB-iMX8MAX
C138 C150 = 22uF,6.3V,X5R: CLABCONF0: SB-iMX8MAX; P/N: 151B22610S
C140 C152 C199 = 100nF,_10V,_X7R,_10%,_0402_2: CLABCONF0: SB-iMX8MAX
C141 C151 C198 = 100nF,_10V,_X7R,_10%,_0402_1: CLABCONF0: SB-iMX8MAX
C278 C279 = 1uF,X5R,6.3V,0402: CLABCONF0: SB-iMX8MAX; P/N: 151D10510S
D3 D5 = BAT54WS_0: CLABCONF0: DNP
D9 D10 = ZENER_24V_500mW_SOD-123: CLABCONF0: DNP
L13 L22 = INC_DELTA_SI43-100,_10uH: CLABCONF0: SB-iMX8MAX; CLABCONF1: <null>; CLABCONF2: <null>; CLABCONF3: <null>; CLABCONF4: <null>; CLABCONF5: <null>; CLABCONF6: <null>; CLABCONF7: <null>; CLABCONF8: <null>; CLABCONF9: <null>
P22 = FPC_Connector_30: CLABCONF0: SB-iMX8MAX; P/N: 182P03002S
P46 P48 = FPC_Connector_8: CLABCONF0: SB-iMX8MAX; P/N: 182P00802S
R36 R185 R266 = 2.2R,5%,0402,1_16W: CLABCONF0: SB-iMX8MAX; P/N: 161C00005S
R39 R184 = 4_0.75K,1%,0402,1_16W: CLABCONF0: SB-iMX8MAX
R40 R66 = 4_0.75K,1%,0402,1_16W_1: CLABCONF0: SB-iMX8MAX
R41 R186 = 2.2R,5%,0402,1_16W_1: CLABCONF0: SB-iMX8MAX; P/N: 161C5R105S
R42 = 0R,_0402_2: CLABCONF0: SB-iMX8MAX
R142 R187 = 0R,_0402_11: CLABCONF0: SB-iMX8MAX
R148 R253 = 0R,_0402_7: CLABCONF0: DNP
R208 R247 = 0R,_0402_8: CLABCONF0: SB-iMX8MAX
R211 = 0R,_0402_14: CLABCONF0: SB-iMX8MAX
R212 = 0R,_0402_15: CLABCONF0: DNP
R215 = 0R,_0402_0: CLABCONF0: DNP; P/N: 161C00005S
R229 R246 = 0R,_0402_3: CLABCONF0: SB-iMX8MAX
R230 R231 = 0R,_0402_5: CLABCONF0: SB-iMX8MAX
R210 R232 = 0R,_0402_9: CLABCONF0: SB-iMX8MAX
R233 R248 = 0R,_0402_10: CLABCONF0: SB-iMX8MAX
R234 R249 = 0R,_0402_12: CLABCONF0: SB-iMX8MAX
R213 R240 = 0R,_0402_13: CLABCONF0: SB-iMX8MAX
R241 = 0R,_0402: CLABCONF0: SB-iMX8MAX
R242 = 0R,_0402_16: CLABCONF0: DNP
R243 = 0R,_0402_6: CLABCONF0: DNP
R244 R254 = 10K,1%,0402,1_16W_0: CLABCONF0: SB-iMX8MAX
R191 R245 = 0R,_0402_4: CLABCONF0: DNP
TP3 = TESTPOINT: CLABCONF0: DNP
U20 U27 = White_LED_Driver_AP3019AKTR-G1: CLABCONF0: SB-iMX8MAX; P/N: 123C40000S
U33 U36 = IP4220CZ6_0: CLABCONF0: SB-iMX8MAX
C32 = 15pF,_50V,_NPO,_5%,_0402_4: CLABCONF0: SB-iMX8MAX; P/N: 151B10400S
C33 = 15pF,_50V,_NPO,_5%,_0402_10: CLABCONF0: SB-iMX8MAX; P/N: 151B10400S
C35 C43 = 15pF,_50V,_NPO,_5%,_0402: CLABCONF0: SB-iMX8MAX; P/N: 151B10400S
C37 = 15pF,_50V,_NPO,_5%,_0402_1: CLABCONF0: SB-iMX8MAX; P/N: 151B10400S
C40 = 15pF,_50V,_NPO,_5%,_0402_3: CLABCONF0: SB-iMX8MAX; P/N: 151B10400S
C42 = 15pF,_50V,_NPO,_5%,_0402_8: CLABCONF0: SB-iMX8MAX; P/N: 151B10400S
C45 C48 = 100nF,_10V,_X7R,_10%,_0402: CLABCONF0: SB-iMX8MAX; P/N: 151B10600S
C46 = 15pF,_50V,_NPO,_5%,_0402_7: CLABCONF0: SB-iMX8MAX; P/N: 151B10400S
C47 = 15pF,_50V,_NPO,_5%,_0402_9: CLABCONF0: SB-iMX8MAX; P/N: 151B10400S
C1082 = 15pF,_50V,_NPO,_5%,_0402_11: CLABCONF0: SB-iMX8MAX; P/N: 151B10400S
C1083 = 15pF,_50V,_NPO,_5%,_0402_6: CLABCONF0: SB-iMX8MAX; P/N: 151B10400S
D4 D12 D13 = 1A_Schottky_Barrier_Rectifier: CLABCONF0: SB-iMX8MAX
P4 = CON_DISPLAYPORT-SINGLE_0: Con, DisplayPort single; CLABCONF0: SB-iMX8MAX; P/N: 180K02000S
Q94 Q95 = DUAL_N-MOSFET,_0.5A_20V: CLABCONF0: SB-iMX8MAX
R31 = 1M_,5%,_0402_4: CLABCONF0: DNP; P/N: 161C20011S
R32 = 1M_,5%,_0402_2: CLABCONF0: SB-iMX8MAX; P/N: 161C20011S
R67 = 1M_,5%,_0402_8: CLABCONF0: DNP; P/N: 161C10021S
R68 = 1M_,5%,_0402_1: CLABCONF0: SB-iMX8MAX; P/N: 161C10031S
R69 = 1M_,5%,_0402_9: CLABCONF0: SB-iMX8MAX; P/N: 161C10031S
R70 = 1M_,5%,_0402_6: CLABCONF0: DNP; P/N: 161C20011S
R71 = 1M_,5%,_0402_7: CLABCONF0: SB-iMX8MAX; P/N: 161C10021S
R72 = 1M_,5%,_0402: CLABCONF0: SB-iMX8MAX; P/N: 161C10031S
R178 = 1M_,5%,_0402_5: CLABCONF0: SB-iMX8MAX; P/N: 161C20011S
R880 = 1M_,5%,_0402_3: CLABCONF0: SB-iMX8MAX; P/N: 161C10021S
R881 = 1M_,5%,_0402_10: CLABCONF0: SB-iMX8MAX; P/N: 161C10021S
R882 = RESISTOR: CLABCONF0: SB-iMX8MAX; P/N: 161C10045S
U2 U3 = IC,ESD_Diode,0.25pF_,x4: CLABCONF0: SB-iMX8MAX; P/N: 132D10020S
U93 U94 = 7SZ05_sgl_OD_inverter,_SC70: CLABCONF0: SB-iMX8MAX
P5 = FPC_40_05mm: CLABCONF0: SB-iMX8MAX; Group: Always
P6 = Conn.,_W2B,_Header,_2x1,_1.25mm: CLABCONF0: SB-iMX8MAX; P/N: 182E00201S
R180 = 0R,_0402_17: CLABCONF0: SB-iMX8MAX
R188 = 2.2R,5%,0402,1_16W_2: CLABCONF0: SB-iMX8MAX; P/N: 161C2R205S
R214 = 0R,_0402_14: CLABCONF0: DNP
R250 = 0R,_0402_15: CLABCONF0: SB-iMX8MAX
R251 = 0R,_0402_16: CLABCONF0: SB-iMX8MAX
R252 = 0R,_0402: CLABCONF0: DNP
R255 = 0R,_0402_2: CLABCONF0: DNP
R256 = 0R,_0402_6: CLABCONF0: SB-iMX8MAX
C50 = 220pF,50V,NPO,0603: CLABCONF0: SB-iMX8MAX
C51 = 10nF,_25V,_X7R,_10%,_0402: CLABCONF0: SB-iMX8MAX
C52 = 100pF,_50V,_NPO,_5%,_0402: CLABCONF0: SB-iMX8MAX
C53 = 10nF,_25V,_X7R,_10%,_0402_1: CLABCONF0: SB-iMX8MAX
C200 = 10uF_10V_20%_0402_1: CLABCONF0: SB-iMX8MAX
C202 = 100nF,_10V,_X7R,_10%,_0402_3: CLABCONF0: SB-iMX8MAX
C205 C206 = 100uF,_6.3V,_X5R,_20%,_1210: CLABCONF0: SB-iMX8MAX; P/N: 151B10730S
C207 = 220pF,50V,NPO,0603_2: CLABCONF0: SB-iMX8MAX
C208 = 220pF,50V,NPO,0603_1: CLABCONF0: SB-iMX8MAX
C209 = 100nF,_10V,_X7R,_10%,_0402_4: CLABCONF0: SB-iMX8MAX
C211 = 10uF_10V_20%_0402_2: CLABCONF0: SB-iMX8MAX
C212 = 10uF_10V_20%_0402_3: CLABCONF0: SB-iMX8MAX
C213 = 10uF_10V_20%_0402: CLABCONF0: SB-iMX8MAX
C214 C215 = 1uF,X5R,6.3V,0402: CLABCONF0: DNP; P/N: 151K33000S
P23 P24 P26 = Audio_JACK,_STEREO+AUX+SW_3.5mm: CLABCONF0: SB-iMX8MAX
R27 = 33R,5%,0402,1_16W_0: CLABCONF0: SB-iMX8MAX
R192 = 5.62K_1%,0402: CLABCONF0: SB-iMX8MAX
R193 = 5.62K_1%,0402_1: CLABCONF0: SB-iMX8MAX
R194 = 5.62K_1%,0402_2: CLABCONF0: SB-iMX8MAX
R195 = 5.62K_1%,0402_3: CLABCONF0: SB-iMX8MAX
R196 = 0R,_0402_0_1: CLABCONF0: SB-iMX8MAX
R216 = 0R,_0402_0: CLABCONF0: DNP
R218 = 47K,_0402_1: CLABCONF0: SB-iMX8MAX
R219 = 47K,_0402_3: CLABCONF0: SB-iMX8MAX; P/N: 161C68001S
R222 = 100R,1%,0402,1_16W_1: CLABCONF0: SB-iMX8MAX
R223 = 220R,5%,0402,1_16W: CLABCONF0: SB-iMX8MAX
R224 = 100R,1%,0402,1_16W_2: CLABCONF0: SB-iMX8MAX
R225 = 100R,1%,0402,1_16W: CLABCONF0: SB-iMX8MAX
R226 = 10K,1%,0402,1_16W: CLABCONF0: SB-iMX8MAX
R227 R261 = 47K,_0402: CLABCONF0: SB-iMX8MAX
R262 = 47K,_0402_2: CLABCONF0: SB-iMX8MAX
R263 = 0R,_0402_0_2: CLABCONF0: SB-iMX8MAX
S2 = MISC_SHORT_NL: CLABCONF0: DNP; P/N: iMX8_SHORT
U28 = TSC2046_2: CLABCONF0: SB-iMX8MAX; P/N: 117A10010S
U29 = 74LCX04_sgl_gate_TSSOP-14: CLABCONF0: SB-iMX8MAX
X5 = TMP_133032: CLABCONF0: DNP; P/N: 141B12604I
J23 = HDMI_Connector: CLABCONF0: SB-iMX8MAX
R33 = 1M_,5%,_0402: CLABCONF0: DNP; P/N: 161C20011S
R228 = 1K,1%,0402,1_16W: CLABCONF0: SB-iMX8MAX; Group: CAN
R257 = 47K,_0402_1: CLABCONF0: SB-iMX8MAX; P/N: 161C27421S
H7-H11 = Mechanical_Hole: CLABCONF0: DNP
H12 H13 = Hole,_Plated,_M2,_5mm._ext.: CLABCONF0: DNP
SCREW1 SCREW2 = SCREW,_M2,_3.5mm,_PAN_HEAD: CLABCONF0: SB-iMX8MAX
SP10 SP11 = SMT_SPACER_M2x3_1: CLABCONF0: SB-iMX8MAX
SPACER1 SPACER2 = Hexagonal_Standoff_0: CLABCONF0: DNP; P/N: 206C10160

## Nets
3V3_AW: C74.1 C79.1 C91.1 C96.1 P11.24(+3.3V_AUX) P11.39(RSVD6) P11.41(RSVD7) P19.24(+3.3V_AUX) P19.39(RSVD6) P19.41(RSVD7) R35.1 R63.1 R65.1 ; also on sheet 9 11 12 13 14 15
3V3_PER: C36.1 C39.1 C73.1 C75.1 C89.1 C92.1 C192.2 C195.2 C197.1 C198.1 C199.1 C200.1 C202.1 C211.1 C212.1 C213.1 C1082.1 D4.2(ANODE) D12.2(ANODE) J11.A9(+3.3V) J11.A10(+3.3V) J11.B8(+3.3V) J11.B10(3.3Vaux) P11.2(+3.3V_1) P11.52(+3.3V_2) P19.2(+3.3V_1) P19.52(+3.3V_2) R32.2 R39.1 R40.1 R64.1 R66.1 R69.2 R71.1 R142.1 R147.2 R163.2 R164.2 R178.2 R180.1 R184.1 R189.2 R197.2 R212.2 R214.2 R229.1 R230.1 U28.3(DCVDD) U28.5(DBVDD) U28.12(HPVDD) U28.18(AVDD) U29.14(VCC) U93.5(VCC) ; also on sheet 9 11 12 13 14 15
5V0_PER: C1083.1 D13.2(ANODE) R33.2 R227.1 R228.2 R266.1 R880.2 R881.2 U94.5(VCC) ; also on sheet 9 11 12 13 15
AGND: C50.1 C52.2 C199.2 C202.2 C207.2 C208.2 C209.2 C210.2 C212.2 C213.2 P23.1(COM) P24.1(COM) P26.1(COM) R193.1 R195.1 R218.2 R223.2 R224.1 R261.2 R262.2 S2.2 U28.15(HPGND) U28.19(AGND) U28.29(PAD)
GND: C36.2 C39.2 C45.1 C48.1 C73.2 C74.2 C75.2 C79.2 C80.2 C81.2 C82.2 C83.1 C84.1 C85.1 C86.1 C89.2 C91.2 C92.2 C93.2 C94.2 C95.2 C96.2 C97.1 C136.2 C138.2 C140.1 C141.1 C144.1 C145.1 C146.1 C147.2 C148.2 C149.1 C150.2 C151.2 C152.1 C190.2 C191.2 C192.1 C194.2 C195.1 C196.2 C197.2 C198.2 C200.2 C211.2 C214.1 C215.1 C278.2 C279.2 C1082.2 C1083.2 H7.1 H8.1 H9.1 H10.1 H11.1 H12.1 H13.1 J11.A4(GND) J11.A12(GND) J11.A15(GND) J11.A18(GND) J11.B4(GND) J11.B7(GND) J11.B13(GND) J11.B16(GND) J11.B18(GND) J23.2(D2_Shield) J23.5(D1_Shield) J23.8(D0_Shield) J23.11(CK_Shield) J23.17(GND) J23.20(SHELL1) J23.21(SHELL2) L9.5(GND) L9.6(GND) L16.5(GND) L16.6(GND) L47.5(GND) L47.6(GND) L48.5(GND) L48.6(GND) L49.5(GND) L49.6(GND) L50.5(GND) L50.6(GND) L51.5(GND) L51.6(GND) L52.5(GND) L52.6(GND) L53.5(GND) L53.6(GND) L54.5(GND) L54.6(GND) L55.5(GND) L55.6(GND) L56.5(GND) L56.6(GND) L57.5(GND) L57.6(GND) L58.5(GND) L58.6(GND) L59.5(GND) L59.6(GND) L60.5(GND) L60.6(GND) L61.5(GND) L61.6(GND) L62.5(GND) L62.6(GND) L63.5(GND) L63.6(GND) L64.5(GND) L64.6(GND) L65.5(GND) L65.6(GND) L66.5(GND) L66.6(GND) L67.5(GND) L67.6(GND) L68.5(GND) L68.6(GND) L69.5(GND) L69.6(GND) P4.2(GND0) P4.5(GND1) P4.8(GND2) P4.11(GND3) P4.16(GND6) P4.19(PWR_RTN) P4.SH1 P4.SH2 P4.SH3 P4.SH4 P5.1 P5.2 P5.5 P5.8 P5.11 P5.14 P5.17 P5.20 P5.23 P5.26 P5.29 P5.32 P5.35 P5.36 P6.M1 P6.M2 P10.5(GND) P10.9(M9) P10.10(M10) P10.11(M11) P10.12(M12) P11.4(GND7) P11.9(GND1) P11.15(GND2) P11.18(GND8) P11.21(GND3) P11.26(GND9) P11.27(GND4) P11.29(GND5) P11.34(GND10) P11.35(GND6) P11.37(RSVD5) P11.40(GND11) P11.50(GND12) P15.5(GND) P15.9(M9) P15.10(M10) P15.11(M11) P15.12(M12) P19.4(GND7) P19.9(GND1) P19.15(GND2) P19.18(GND8) P19.21(GND3) P19.26(GND9) P19.27(GND4) P19.29(GND5) P19.34(GND10) P19.35(GND6) P19.37(RSVD5) P19.40(GND11) P19.50(GND12) P22.6 P22.9 P22.12 P22.15 P22.18 P22.21 P22.22 P22.24 P22.29 P22.30 R25.1 R31.1 R36.2 R67.2 R68.1 R70.1 R72.1 R108.2 R109.2 R169.2 R170.2 R185.2 R234.1 R241.1 R250.1 R251.1 R882.1 S2.1 SP10.1 SP11.1 U2.3(Vn) U2.8(Vn) U3.3(Vn) U3.8(Vn) U20.2(GND) U27.2(GND) U28.4(DGND) U28.25(MODE) U28.26(CSB) U29.7(GND) U93.3(GND) U94.3(GND) X5.2(GND) X5.4(GND) ; also on sheet 9 10 11 12 13 14 15
A_IN: C53.2 R225.2
ADCLRC: R196.1 R216.1 U28.11(ADCLRC)
AMP_IN: R225.1 R226.2 U29.3(I)
AMP_OUT: R226.1 U29.1(I) U29.4(12)
AMPR: C49.2 R217.1
AUD_VMID: C209.1 C210.1 U28.20(VMID)
AUDIO_IN_DIG: C53.1 P24.2(AUX) P24.CO R224.2
AUDIO_OUT_DIG: C52.1 P23.2(AUX) R222.2 R223.1
CDC_BCLK: R27.2 U28.7(BCLK)
CDC_MCLK: C214.2 R263.1 U28.1(XTI/MCLK) X5.1
CODEC_XTALOUT: C215.2 U28.2(XTO) X5.3
DP_AUXN_DATA: P4.17(AUX_CHn) Q94.3(D2) Q95.3(D2) R69.1 U2.2(CH2) U2.9(NC)
DP_AUXP_CLK: P4.15(AUX_CHp) Q94.6(D1) Q95.1(S1) R68.2 U2.1(CH1) U2.10(NC)
DP_CNFG1: P4.13(CNFG1) R882.2 U2.4(CH3) U2.7(NC) U93.2(IN)
DP_CNFG1_A: Q94.2(G1) Q94.5(G2) R880.1 U93.4(OUT) U94.2(IN)
DP_CNFG1_B: Q95.2(G1) Q95.5(G2) R881.1 U94.4(OUT)
DP_PWR: C45.2 D4.1(CATHODE) P4.20(DP_PWR)
DSI0_BCKLIGHT_FB: D9.2(ANODE) R42.2 U20.3(FB)
DSI0_DISP_IO: C140.2 C190.1 P22.27 R147.1 R148.2
DSI0_DISP_PWR: C141.2 C191.1 P22.28 R142.2
DSI0_DISP_RESET: P22.26 R215.1 ; also on sheet 13
DSI0_FPC8_GND: P46.8 R234.2
DSI0_FPC_GND: P46.1 R241.2 U33.2(GND)
DSI0_FPC_INT: P46.6 R233.2 R242.2 U33.3(IO2)
DSI0_FPC_RES#: P46.7 R240.2 R243.2 U33.1(IO1)
DSI0_FPC_SCL: P46.4 R231.2 U33.4(IO3)
DSI0_FPC_SDA: P46.5 R232.2 U33.6(IO4)
DSI0_FPC_VDD: P46.3 R229.2 U33.5(VBUS)
DSI0_INT_GPIO: R242.1 ; also on sheet 13
DSI0_LED_A: C278.1 D3.CATHODE D9.1(CATHODE) P22.4 U20.5(VOUT)
DSI0_LED_EN: R211.2 R244.2 R245.2 U20.4(CTRL)
DSI0_LED_GPIO: R245.1 ; also on sheet 13
DSI0_LED_K: P22.2 R41.1 R42.1
DSI0_TS_RESET: R240.1 ; also on sheet 13
DSI0_V_LED: C136.1 C138.1 L13.1 R208.2 R212.1 R244.1 U20.6(VIN)
DSI0_WLD_RES: R36.1 R41.2
DSI0_WLD_SW: D3.ANODE L13.2 U20.1(SW)
DSI_CLN: L48.2 P22.13
DSI_CLP: L48.1 P22.14
DSI_N0: L51.2 P22.7
DSI_N1: L47.2 P22.10
DSI_N2: L49.2 P22.16
DSI_N3: L50.2 P22.19
DSI_P0: L51.1 P22.8
DSI_P1: L47.1 P22.11
DSI_P2: L49.1 P22.17
DSI_P3: L50.1 P22.20
GPIO_SATA_PCIe_SEL: P19.43(RSVD8) R64.2 ; also on sheet 9
HDMI_PWR: C48.2 D13.1(CATHODE) J23.18(+5V)
HDMI_RX_ARC_P: C43.2 ; also on sheet 9
HDMI_RX_ARC_P_C: C43.1 J23.14(NC) U3.2(CH2) U3.9(NC)
HDMI_RX_CEC: J23.13(CE_Remote) R257.1 U3.1(CH1) U3.10(NC) ; also on sheet 9
HDMI_RX_CEC_R: D12.1(CATHODE) R257.2
HDMI_RX_CLK_N: L67.3 ; also on sheet 9
HDMI_RX_CLK_N_F: J23.12(CK-) L67.2
HDMI_RX_CLK_P: L67.4 ; also on sheet 9
HDMI_RX_CLK_P_F: J23.10(CK+) L67.1
HDMI_RX_DAT0_N: L65.3 ; also on sheet 9
HDMI_RX_DAT0_N_F: J23.9(D0-) L65.2
HDMI_RX_DAT0_P: L65.4 ; also on sheet 9
HDMI_RX_DAT0_P_F: J23.7(D0+) L65.1
HDMI_RX_DAT1_N: L69.3 ; also on sheet 9
HDMI_RX_DAT1_N_F: J23.6(D1-) L69.2
HDMI_RX_DAT1_P: L69.4 ; also on sheet 9
HDMI_RX_DAT1_P_F: J23.4(D1+) L69.1
HDMI_RX_DAT2_N: L68.3 ; also on sheet 9
HDMI_RX_DAT2_N_F: J23.3(D2-) L68.2
HDMI_RX_DAT2_P: L68.4 ; also on sheet 9
HDMI_RX_DAT2_P_F: J23.1(D2+) L68.1
HDMI_RX_DDC_SCL: J23.15(DDC_CLK) R227.2 ; also on sheet 9
HDMI_RX_DDC_SDA: J23.16(DDC_DATA) R33.1 ; also on sheet 9
HDMI_RX_HPD: J23.19(HP_DET) R228.1 U3.5(CH4) U3.6(NC) ; also on sheet 9
HDMI_RX_MON_5V: R266.2 ; also on sheet 9
HDMI_TX_AUX_N: C47.2 ; also on sheet 9
HDMI_TX_AUX_N_C: C47.1 Q94.4(S2)
HDMI_TX_AUX_P: C46.2 ; also on sheet 9
HDMI_TX_AUX_P_C: C46.1 Q94.1(S1)
HDMI_TX_CEC: P4.14(CNFG2) R67.1 R71.2 ; also on sheet 9
HDMI_TX_CLK_DP3_N: C42.2 ; also on sheet 9
HDMI_TX_CLK_DP3_P: C41.2 ; also on sheet 9
HDMI_TX_DAT0_DP2_N: C40.2 ; also on sheet 9
HDMI_TX_DAT0_DP2_P: C38.2 ; also on sheet 9
HDMI_TX_DAT1_DP1_N: C37.2 ; also on sheet 9
HDMI_TX_DAT1_DP1_P: C35.2 ; also on sheet 9
HDMI_TX_DAT2_DP0_N: C33.2 ; also on sheet 9
HDMI_TX_DAT2_DP0_P: C32.2 ; also on sheet 9
HDMI_TX_DDC_SCL: Q95.6(D1) R31.2 R32.1 ; also on sheet 9
HDMI_TX_DDC_SDA: Q95.4(S2) R70.2 R178.1 ; also on sheet 9
HDMI_TX_DP0_N_C: C33.1 L52.3
HDMI_TX_DP0_N_CF: L52.2 P4.3(ML_Lane_0n)
HDMI_TX_DP0_P_C: C32.1 L52.4
HDMI_TX_DP0_P_CF: L52.1 P4.1(ML_Lane_0p)
HDMI_TX_DP1_N_C: C37.1 L53.3
HDMI_TX_DP1_N_CF: L53.2 P4.6(ML_Lane_1n)
HDMI_TX_DP1_P_C: C35.1 L53.4
HDMI_TX_DP1_P_CF: L53.1 P4.4(ML_Lane_1p)
HDMI_TX_DP2_N_C: C40.1 L54.3
HDMI_TX_DP2_N_CF: L54.2 P4.9(ML_Lane_2N)
HDMI_TX_DP2_P_C: C38.1 L54.4
HDMI_TX_DP2_P_CF: L54.1 P4.7(ML_Lane_2p)
HDMI_TX_DP3_N_C: C42.1 L55.3
HDMI_TX_DP3_N_CF: L55.2 P4.12(ML_Lane_3n)
HDMI_TX_DP3_P_C: C41.1 L55.4
HDMI_TX_DP3_P_CF: L55.1 P4.10(ML_Lane_3p)
HDMI_TX_HPD: P4.18(Hot_Plug) R72.2 U2.5(CH4) U2.6(NC) ; also on sheet 9
LHPOUT: C206.1 P23.4(L) R261.1
LHPOUT_C: C206.2 U28.13(LHPOUT)
LLINEIN: P24.4(L) R194.2
LLINEIN_C: C204.1 U28.24(LLINEIN)
LLINEIN_R: C204.2 C207.1 R193.2 R194.1
LVDS0_BCKLIGHT_FB: D10.2(ANODE) R187.2 U27.3(FB)
LVDS0_BL_PWM: R213.1 ; also on sheet 9
LVDS0_CH0_CLK_N: L59.4 ; also on sheet 9
LVDS0_CH0_CLK_N_F: L59.1 P5.25
LVDS0_CH0_CLK_P: L59.3 ; also on sheet 9
LVDS0_CH0_CLK_P_F: L59.2 P5.24
LVDS0_CH0_TX0_N: L56.4 ; also on sheet 9
LVDS0_CH0_TX0_N_F: L56.1 P5.34
LVDS0_CH0_TX0_P: L56.3 ; also on sheet 9
LVDS0_CH0_TX0_P_F: L56.2 P5.33
LVDS0_CH0_TX1_N: L57.4 ; also on sheet 9
LVDS0_CH0_TX1_N_F: L57.1 P5.31
LVDS0_CH0_TX1_P: L57.3 ; also on sheet 9
LVDS0_CH0_TX1_P_F: L57.2 P5.30
LVDS0_CH0_TX2_N: L58.4 ; also on sheet 9
LVDS0_CH0_TX2_N_F: L58.1 P5.28
LVDS0_CH0_TX2_P: L58.3 ; also on sheet 9
LVDS0_CH0_TX2_P_F: L58.2 P5.27
LVDS0_CH0_TX3_N: L60.4 ; also on sheet 9
LVDS0_CH0_TX3_N_F: L60.1 P5.22
LVDS0_CH0_TX3_P: L60.3 ; also on sheet 9
LVDS0_CH0_TX3_P_F: L60.2 P5.21
LVDS0_CH1_CLK_N: L64.4 ; also on sheet 9
LVDS0_CH1_CLK_N_F: L64.1 P5.10
LVDS0_CH1_CLK_P: L64.3 ; also on sheet 9
LVDS0_CH1_CLK_P_F: L64.2 P5.9
LVDS0_CH1_TX0_N: L61.4 ; also on sheet 9
LVDS0_CH1_TX0_N_F: L61.1 P5.19
LVDS0_CH1_TX0_P: L61.3 ; also on sheet 9
LVDS0_CH1_TX0_P_F: L61.2 P5.18
LVDS0_CH1_TX1_N: L62.4 ; also on sheet 9
LVDS0_CH1_TX1_N_F: L62.1 P5.16
LVDS0_CH1_TX1_P: L62.3 ; also on sheet 9
LVDS0_CH1_TX1_P_F: L62.2 P5.15
LVDS0_CH1_TX2_N: L63.4 ; also on sheet 9
LVDS0_CH1_TX2_N_F: L63.1 P5.13
LVDS0_CH1_TX2_P: L63.3 ; also on sheet 9
LVDS0_CH1_TX2_P_F: L63.2 P5.12
LVDS0_CH1_TX3_N: L66.4 ; also on sheet 9
LVDS0_CH1_TX3_N_F: L66.1 P5.7
LVDS0_CH1_TX3_P: L66.3 ; also on sheet 9
LVDS0_CH1_TX3_P_F: L66.2 P5.6
LVDS0_DISP_IO: C152.2 C196.1 R189.1 R191.2 R256.1
LVDS0_DISP_PWR: C149.2 C194.1 P5.37 P5.38 R180.2
LVDS0_FPC8_GND: P48.8 R250.2
LVDS0_FPC_GND: P48.1 R251.2 U36.2(GND)
LVDS0_FPC_INT: P48.6 R247.2 R252.2 U36.3(IO2)
LVDS0_FPC_RES#: P48.7 R249.2 R253.2 U36.1(IO1)
LVDS0_FPC_SCL: P48.4 R246.2 U36.4(IO3)
LVDS0_FPC_SDA: P48.5 R248.2 U36.6(IO4)
LVDS0_FPC_VDD: P48.3 R230.2 U36.5(VBUS)
LVDS0_FPC_VDDIO: P48.2 R256.2
LVDS0_INT_GPIO: R252.1 ; also on sheet 13
LVDS0_LED_A: C279.1 D5.CATHODE D10.1(CATHODE) P6.2 U27.5(VOUT)
LVDS0_LED_EN: R213.2 R254.2 R255.2 U27.4(CTRL)
LVDS0_LED_GPIO: R255.1 ; also on sheet 13
LVDS0_LED_K: P6.1 R186.1 R187.1 R188.1
LVDS0_TS_INT: R247.1 ; also on sheet 9
LVDS0_TS_RESET: R249.1 ; also on sheet 13
LVDS0_TS_SCL: R66.2 R246.1 ; also on sheet 9
LVDS0_TS_SDA: R184.2 R248.1 ; also on sheet 9
LVDS0_V_LED: C150.1 C151.1 L22.1 R210.2 R214.1 R254.1 U27.6(VIN)
LVDS0_WLD_RES: R185.1 R186.2 R188.2
LVDS0_WLD_SW: D5.ANODE L22.2 U27.1(SW)
MCLK_OUT0: R263.2 ; also on sheet 9
MIC_IN: C49.1 C50.2 P26.4(L) R218.1 R219.2
MICBIAS: R219.1 U28.21(MICBIAS)
MICIN: R217.2 U28.22(MICIN)
MINI_PCIE_USB_DN: L9.3 P11.36(USB_D-)
MINI_PCIE_USB_DP: L9.4 P11.38(USB_D+)
MIPI_DSI0_CLK_N: L48.3 ; also on sheet 9
MIPI_DSI0_CLK_P: L48.4 ; also on sheet 9
MIPI_DSI0_DATA0_N: L51.3 ; also on sheet 9
MIPI_DSI0_DATA0_P: L51.4 ; also on sheet 9
MIPI_DSI0_DATA1_N: L47.3 ; also on sheet 9
MIPI_DSI0_DATA1_P: L47.4 ; also on sheet 9
MIPI_DSI0_DATA2_N: L49.3 ; also on sheet 9
MIPI_DSI0_DATA2_P: L49.4 ; also on sheet 9
MIPI_DSI0_DATA3_N: L50.3 ; also on sheet 9
MIPI_DSI0_DATA3_P: L50.4 ; also on sheet 9
MIPI_DSI0_I2C_SCL: R39.2 R231.1 ; also on sheet 9
MIPI_DSI0_I2C_SDA: R40.2 R232.1 ; also on sheet 9
MIPI_DSI0_INT: R233.1 ; also on sheet 9
MIPI_DSI0_PWM: R211.1 ; also on sheet 9
mPCIE_CLK_REQn: P11.7(CLKREQ#) ; also on sheet 9
mPCIE_REF_CLKN: P11.11(REFCLK-) R108.1 ; also on sheet 9
mPCIE_REF_CLKP: P11.13(REFCLK+) R109.1 ; also on sheet 9
mPCIE_RSTn: P11.22(PERST#) ; also on sheet 9
mPCIE_RXN: P11.23(PER_N0) ; also on sheet 9
mPCIE_RXP: P11.25(PER_P0) ; also on sheet 9
mPCIE_TXN: P11.31(PET_N0) ; also on sheet 9
mPCIE_TXP: P11.33(PET_P0) ; also on sheet 9
mPCIe_USB_DN: L9.2 ; also on sheet 9
mPCIe_USB_DP: L9.1 ; also on sheet 9
mPCIE_WAKEn: P11.1(WAKE#) R35.2 ; also on sheet 9
mSATA_mPCIE_USB_DN: L16.3 P19.36(USB_D-)
mSATA_mPCIE_USB_DP: L16.4 P19.38(USB_D+)
PCIE1_CLKGEN1_N: J11.A14(REFCLK-) ; also on sheet 9
PCIE1_CLKGEN1_P: J11.A13(REFCLK+) ; also on sheet 9
PCIE1_CLKREQ#: R25.2 ; also on sheet 9
PCIE1_PERST#: R172.1 R174.1 R197.1 ; also on sheet 9
PCIE1_PERST#_R: J11.A11(PERST#) R174.2
PCIE1_RX0_N: J11.A17(HSIn(0)) ; also on sheet 9
PCIE1_RX0_P: J11.A16(HSIp(0)) ; also on sheet 9
PCIE1_TX0_N: J11.B15(HSOn(0)) ; also on sheet 9
PCIE1_TX0_P: J11.B14(HSOp(0)) ; also on sheet 9
PCIE1_WAKE#: R171.2 R173.2 ; also on sheet 9
PCIE1_WAKE#_R: J11.B11(WAKE#) R65.2 R173.1
PCIE_SATA_CLKGEN0_N: P19.11(REFCLK-) R170.1 ; also on sheet 9
PCIE_SATA_CLKGEN0_P: P19.13(REFCLK+) R169.1 ; also on sheet 9
PCIE_SATA_CLKREQ#: P19.7(CLKREQ#) ; also on sheet 9
PCIE_SATA_RST#: P19.22(PERST#) R172.2
PCIE_SATA_RX0_N: P19.23(PER_N0) ; also on sheet 9
PCIE_SATA_RX0_P: P19.25(PER_P0) ; also on sheet 9
PCIE_SATA_TX0_N: P19.31(PET_N0) ; also on sheet 9
PCIE_SATA_TX0_P: P19.33(PET_P0) ; also on sheet 9
PCIE_SATA_WAKEn: P19.1(WAKE#) R63.2 R171.1
POR_B_1V8: R215.2 R243.1 R253.1 ; also on sheet 9 11 12
RHPOUT: C205.1 P23.3(R) R262.1
RHPOUT_C: C205.2 U28.14(RHPOUT)
RLINEIN: P24.3(R) R192.2
RLINEIN_C: C203.1 U28.23(RLINEIN)
RLINEIN_R: C203.2 C208.1 R192.1 R195.2
SAI1_RXD: U28.10(ADCDAT) ; also on sheet 9
SAI1_RXFS: R216.2 ; also on sheet 9
SAI1_TXC: R27.1 ; also on sheet 9
SAI1_TXD: U28.8(DACDAT) ; also on sheet 9
SAI1_TXFS: R196.2 U28.9(DACLRC) ; also on sheet 9
SIM1_CLK: C84.2 P10.3(CLK) P11.12(UIM_CLK)
SIM1_IO: P10.7(IO) P11.10(UIM_DATA)
SIM1_RST: C85.2 P10.2(RST) P11.14(UIM_RESET)
SIM1_VCC: C86.2 P10.1(VCC) P11.8(UIM_PWR)
SIM1_VPP: C83.2 P10.6(VPP) P11.16(UIM_VPP)
SIM2_CLK: C145.2 P15.3(CLK) P19.12(UIM_CLK)
SIM2_IO: P15.7(IO) P19.10(UIM_DATA)
SIM2_RST: C144.2 P15.2(RST) P19.14(UIM_RESET)
SIM2_VCC: C146.2 P15.1(VCC) P19.8(UIM_PWR)
SIM2_VPP: C97.2 P15.6(VPP) P19.16(UIM_VPP)
SM_CLK: J11.B5(SMCLK) R198.1
SM_DAT: J11.B6(SMDAT) R203.1
SPDIF_OUT1C: C51.1 R222.1
SPDIF_RX: U29.2(12) ; also on sheet 9
SPDIF_TX: C51.2 ; also on sheet 9
SYS_I2C_SCL: P11.30(SMB_CLK) P19.30(SMB_CLK) R198.2 U28.28(SCLK) ; also on sheet 9 11 13 14
SYS_I2C_SDA: P11.32(SMB_DATA) P19.32(SMB_DATA) R203.2 U28.27(SDIN) ; also on sheet 9 11 13 14
TP3: P22.25 TP3.1
USB_HUB1_DN: L16.2 ; also on sheet 11
USB_HUB1_DP: L16.1 ; also on sheet 11
V_SOM: R208.1 R210.1 ; also on sheet 9 13 15
VDC_IN: C147.1 C148.1 J11.A2(+12V) J11.A3(+12V) J11.B1(+12V) J11.B2(+12V) ; also on sheet 15
VSB_1V5: C80.1 C81.1 C82.1 C93.1 C94.1 C95.1 P11.6(+1.5V_1) P11.28(+1.5V_2) P11.48(+1.5V_3) P19.6(+1.5V_1) P19.28(+1.5V_2) P19.48(+1.5V_3) ; also on sheet 9 13
VSB_1V8: R148.1 R191.1 ; also on sheet 9 12 13 14
W1_DISABLE#: P11.20(RSVD18) R163.1
W2_DISABLE#: P19.20(RSVD18) R164.1

Not connected (* = marked no-connect by the designer): FID1 1*; FID2 1*; FID3 1*; FID4 1*; FID5 1*; FID6 1*; J11 A1(PRSNT#1)* A5(JTAG2)* A6(JTAG3)* A7(JTAG4)* A8(JTAG5)* B3(RSVD0)* B9(JTAG1)* B12(RSVD1)* B17(PRSNT#2)* X1* X2*; P5 3* 4* 39* 40*; P10 4(RSVD4)* 8(RSVD8)*; P11 3(RSVD1)* 5(RSVD2)* 17(RSVD3)* 19(RSVD4)* 42(LED_WWAN#)* 43(RSVD8)* 44(LED_WLAN#)* 45(RSVD9)* 46(LED_WPAN#)* 47(RSVD10)* 49(RSVD11)* 51(RSVD12)*; P15 4(RSVD4)* 8(RSVD8)*; P19 3(RSVD1)* 5(RSVD2)* 17(RSVD3)* 19(RSVD4)* 42(LED_WWAN#)* 44(LED_WLAN#)* 45(RSVD9)* 46(LED_WPAN#)* 47(RSVD10)* 49(RSVD11)* 51(RSVD12)*; P22 1* 3* 5* 23*; P23 CN* CO*; P24 CN*; P26 2(AUX)* 3(R)* CN* CO*; P46 2*; U3 4(CH3)* 7(NC)*; U28 6(CLKOUT)* 16(LOUT)* 17(ROUT)*

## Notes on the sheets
sheet 1
- HDMI RX
- HDMI
- DNP
- 5V0_PER:  0.1+ A
sheet 2
- CODEC
- Place C200 and C197
  ACAP to U28 pins 5 and 4
- Place C213 and C202
  ACAP to U28 pins 12 and 15
- Place C211 and C198
  ACAP to U28 pins 3 and 4
- Place C199 and C212
  ACAP to U28 pins 18 and 19
- MIC IN
- MIC IN
- I2C ADDRESS: 0b0011010 (0x1AH)
- DNP
- AUDIO OUT
- AUDIO IN
- DNP
- 20mil
- 20mil
- DNP
- Keep S1 close to U11
  S1 width at least 20 mil
- DNP
sheet 3
- LVDS 2CH DISPLAY PANEL
- numbering is in opposite direction than display DS bacause connector pins enumeration
- Touchscreen
- DNP
- White LED Driver
- I2C addres:0xBA/0xBB or 0x28/0x29
- Typical LED configuration: Two parallel chains of 6 serially connected LEDs
- DNP
- DNP
- VOUT=25.6V
- I2C for touchscreen
- DNP
- DNP
- 3.3V
- VFB=200mV
- DNP
- 1.8V
- R1=200mV/ILED=200mV/120mA=1.67 ohm
- DNP
sheet 4
- DISPLAYPORT DUAL MODE (DP++)
- Place all 100nF near DP conn.
- DP++
- 3.3VS:  0.5 A
- DNP
- DNP
- DNP
sheet 5
- mini PCIe & SIM
- DNP
- DNP
- Validate if those resistors
  required after bring up
- DNP
- PCIe X1 SLOT
- 3.3V_AUX
- 3.3V_AUX
- PCIe x1 12V RAIL
  peak current = 0.5A
- PCIe x1 3.3V RAIL
  peak current = 3A
- Concraft;0717A0BA56C
- 11.75-12.25V
- 11.75-12.25V
- mSATA / mini PCIe & SIM
- DNP
- DNP
- DNP
- Validate if those resistors
  required after bring up
- DNP
- PD
- 3.3V_AUX
- 3.3V_AUX
- Concraft;0717A0BA56C
- Pin 43 - NC for mSATA, GND for mini PCIe
sheet 6
- MIPI-DSI LCD
- TFT
- place P22-27 not too far from VSB_1V8
- diff 100 ohm
- diff 100 ohm
- diff 100 ohm
- diff 100 ohm
- diff 100 ohm
- diff 100 ohm
- diff 100 ohm
- diff 100 ohm
- diff 100 ohm
- diff 100 ohm
- TE
- RESET
- 3.3V
- IOVCC
- VCI
- 1.8V
- DNP
- DNP
- Touchscreen
- I2C addres:0xBA/0xBB or 0x28/0x29
- White LED Driver
- Typical LED configuration: Two parallel chains of 6 serially connected LEDs
- DNP
- I2C for touchscreen
- DNP
- VOUT=19.2V
- DNP
- 3.3V
- DNP
- 1.8V
- DNP
- VFB=200mV
- DNP
- R1=200mV/ILED=200mV/40mA=5 ohm
sheet 7
- mPCIe SPACER
- mSATA/mPCIe SPACER
- DNP
- DNP
- SB-iMX8MAX SPACERS
sheet 8
- Block Diagram
- SB-iMX8MAX
- BOARD REVISION: 1.1
- PAGE
- FUNCTION
- 01
- BLOCK & POWER DIAGRAM
- 02
- CARRIER BOARD INTERFACE
- 03
- ETHERNET
- 04
- USB
- 05
- PCIe , SATA
- 06
- JTAG, 100 MIL CONN
- 07
- CSI, CAN, GPIO EXP
- 08
- UART, RS232, RS485, EEPROM, SD
- 09
- POWER
- 10
- MIPI-DSI
- 11
- DISPLAYPORT DUAL MODE
- 12
- LVDS 2CH DISPLAY
- 13
- AUDIO
- 14
- HDMI_RX
- 15
- MECHNICS
